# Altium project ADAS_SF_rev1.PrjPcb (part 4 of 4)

## Sheet ADAS_SF_Data_Connection_Radar_02.SchDoc
size 431 x 279 mm; Date: Not shown in title block; ApprovedBy: Not shown in title block; CheckedBy: Not shown in title block; Author: Not shown in title block; CompanyName: Not shown in title block; Engineer: Not shown in title block; Organization: Not shown in title block; Address1: Not shown in title block; Address2: Not shown in title block; Address3: Not shown in title block; Address4: Not shown in title block; DocumentNumber: 1; Revision: Use project parameter SCH_Rev; SheetNumber: 11; SheetTotal: 15; PageSetup: Record=PageOptions¦CenterHorizontal=True¦CenterVertical=True¦PrintScale=1.00¦XCorrection=1.00¦YCorrection=1.00¦PrintKind=0¦BorderSize=5000000¦LeftOffset=0¦BottomOffset=0¦Orientation=2¦PaperLength=1000¦PaperWidth=1000¦Scale=100¦PaperSource=15¦PrintQuality=600¦MediaType=1¦DitherType=10¦PaperKind=Letter¦PrintScaleMode=1
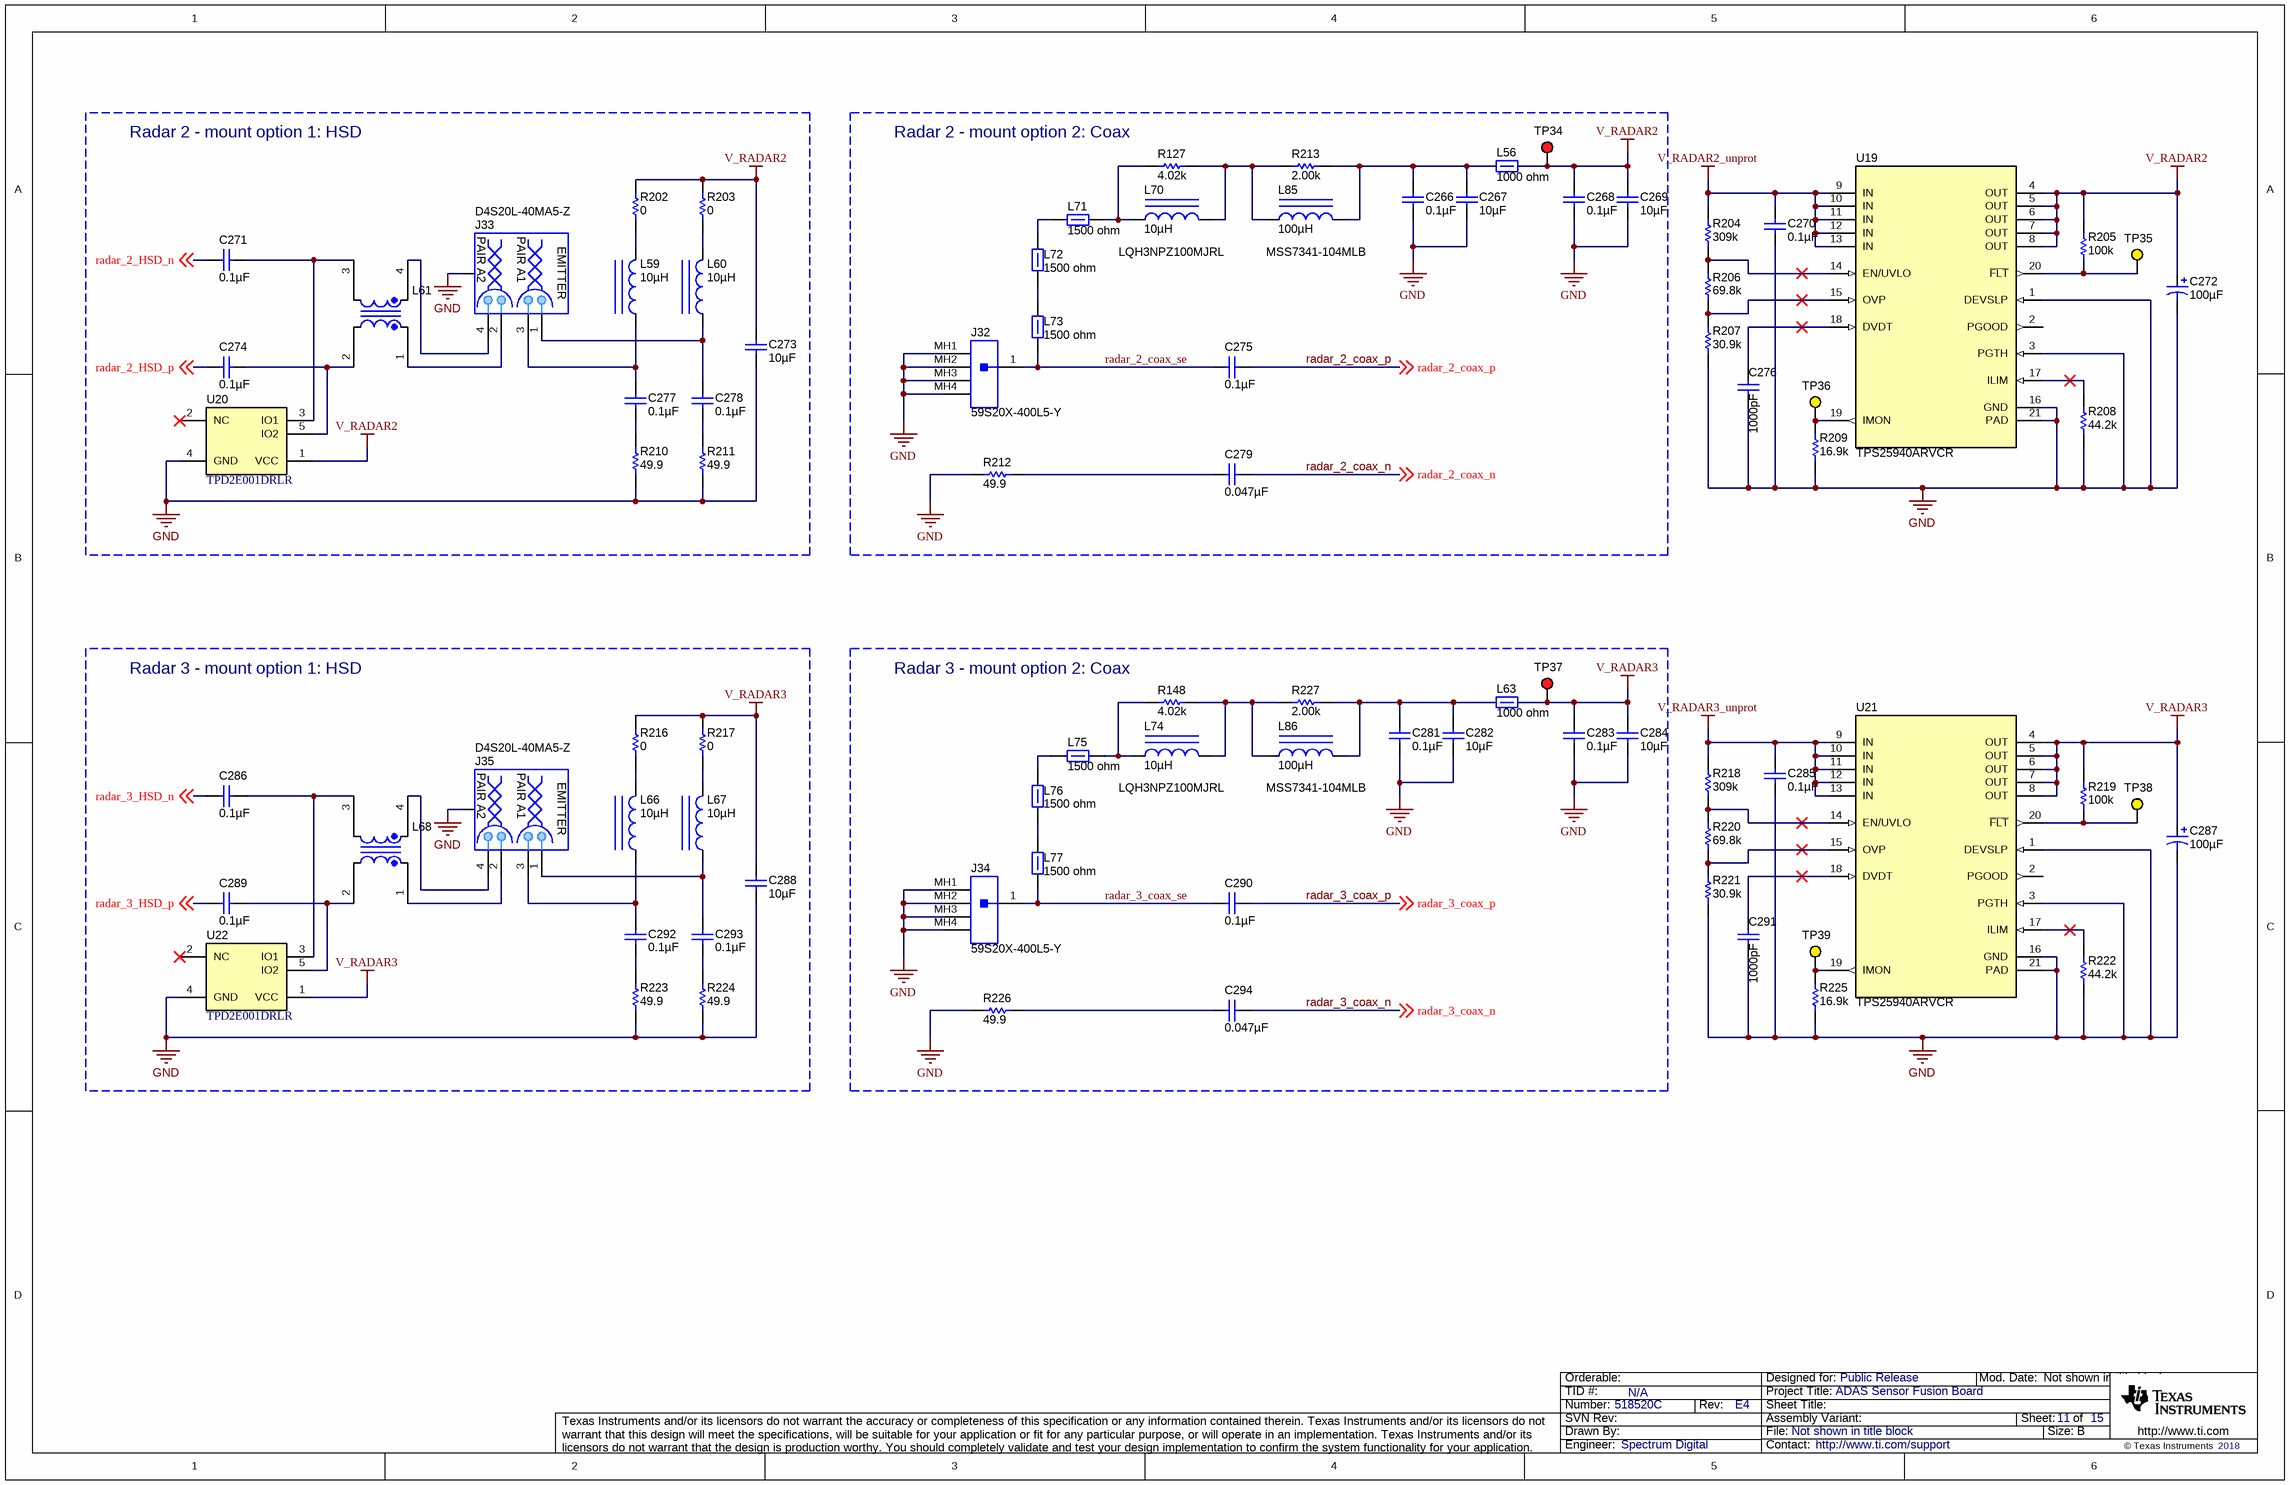
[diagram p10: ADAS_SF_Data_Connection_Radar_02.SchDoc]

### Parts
C266  ValueDisplayed: 0.1µF  [0402]  (hidden comment: GCM155R71H104KE02D)
C267  ValueDisplayed: 10µF  [0805_HV]  (hidden comment: TMK212BBJ106KG-T)
C268  ValueDisplayed: 0.1µF  [0402]  (hidden comment: GCM155R71H104KE02D)
C269  ValueDisplayed: 10µF  [0805_HV]  (hidden comment: TMK212BBJ106KG-T)
C270  ValueDisplayed: 0.1µF  [0603L]  (hidden comment: GRM188R72A104KA35D)
C271  ValueDisplayed: 0.1µF  [0402]  (hidden comment: GCM155R71H104KE02D)
C272  ValueDisplayed: 100µF  [SM_RADIAL_E]  (hidden comment: EEE-FC1C101P)
C273  ValueDisplayed: 10µF  [0805_HV]  (hidden comment: CL21A106KAFN3NE)
C274  ValueDisplayed: 0.1µF  [0402]  (hidden comment: GCM155R71H104KE02D)
C275  ValueDisplayed: 0.1µF  [0402]  (hidden comment: GCM155R71H104KE02D)
C276  ValueDisplayed: 1000pF  [0402]  (hidden comment: GCM155R71H102KA37D)
C277  ValueDisplayed: 0.1µF  [0603]  (hidden comment: GRM188R72A104KA35D)
C278  ValueDisplayed: 0.1µF  [0603]  (hidden comment: GRM188R72A104KA35D)
C279  ValueDisplayed: 0.047µF  [0402]  (hidden comment: CGA2B3X7R1H473K050BB)
C281  ValueDisplayed: 0.1µF  [0402]  (hidden comment: GCM155R71H104KE02D)
C282  ValueDisplayed: 10µF  [0805_HV]  (hidden comment: TMK212BBJ106KG-T)
C283  ValueDisplayed: 0.1µF  [0402]  (hidden comment: GCM155R71H104KE02D)
C284  ValueDisplayed: 10µF  [0805_HV]  (hidden comment: TMK212BBJ106KG-T)
C285  ValueDisplayed: 0.1µF  [0603L]  (hidden comment: GRM188R72A104KA35D)
C286  ValueDisplayed: 0.1µF  [0402]  (hidden comment: GCM155R71H104KE02D)
C287  ValueDisplayed: 100µF  [SM_RADIAL_E]  (hidden comment: EEE-FC1C101P)
C288  ValueDisplayed: 10µF  [0805_HV]  (hidden comment: CL21A106KAFN3NE)
C289  ValueDisplayed: 0.1µF  [0402]  (hidden comment: GCM155R71H104KE02D)
C290  ValueDisplayed: 0.1µF  [0402]  (hidden comment: GCM155R71H104KE02D)
C291  ValueDisplayed: 1000pF  [0402]  (hidden comment: GCM155R71H102KA37D)
C292  ValueDisplayed: 0.1µF  [0603]  (hidden comment: GRM188R72A104KA35D)
C293  ValueDisplayed: 0.1µF  [0603]  (hidden comment: GRM188R72A104KA35D)
C294  ValueDisplayed: 0.047µF  [0402]  (hidden comment: CGA2B3X7R1H473K050BB)
J32  59S20X-400L5-Y  [Rosenberger_59S20X-400L5]
J33  D4S20L-40MA5-Z  [Rosenberger_D4S20L-40MA5]
J34  59S20X-400L5-Y  [Rosenberger_59S20X-400L5]
J35  D4S20L-40MA5-Z  [Rosenberger_D4S20L-40MA5]
L56  value 1000 ohm  [0603]  (hidden comment: MPZ1608S102ATA00)
L59  ValueDisplayed: 10µH  [EPL3012]  (hidden comment: EPL3012-103MLB)
L60  ValueDisplayed: 10µH  [EPL3012]  (hidden comment: EPL3012-103MLB)
L61  DLW21HN900SQ2L  [DLW21H]  (value not drawn)
L63  value 1000 ohm  [0603]  (hidden comment: MPZ1608S102ATA00)
L66  ValueDisplayed: 10µH  [EPL3012]  (hidden comment: EPL3012-103MLB)
L67  ValueDisplayed: 10µH  [EPL3012]  (hidden comment: EPL3012-103MLB)
L68  DLW21HN900SQ2L  [DLW21H]  (value not drawn)
L70  LQH3NPZ100MJRL  ValueDisplayed: 10µH  [LQH3NPZ_JR]
L71  ValueDisplayed: 1500 ohm  [0603]  (hidden comment: BLM18HE152SN1D)
L72  ValueDisplayed: 1500 ohm  [0603]  (hidden comment: BLM18HE152SN1D)
L73  ValueDisplayed: 1500 ohm  [0603]  (hidden comment: BLM18HE152SN1D)
L74  LQH3NPZ100MJRL  ValueDisplayed: 10µH  [LQH3NPZ_JR]
L75  ValueDisplayed: 1500 ohm  [0603]  (hidden comment: BLM18HE152SN1D)
L76  ValueDisplayed: 1500 ohm  [0603]  (hidden comment: BLM18HE152SN1D)
L77  ValueDisplayed: 1500 ohm  [0603]  (hidden comment: BLM18HE152SN1D)
L85  MSS7341-104MLB  ValueDisplayed: 100µH  [MSS7341]
L86  MSS7341-104MLB  ValueDisplayed: 100µH  [MSS7341]
R127  ValueDisplayed: 4.02k  [0603]  (hidden comment: CRCW06034K02FKEA)
R148  ValueDisplayed: 4.02k  [0603]  (hidden comment: CRCW06034K02FKEA)
R202  ValueDisplayed: 0  [0603]  (hidden comment: CRCW06030000Z0EA)
R203  ValueDisplayed: 0  [0603]  (hidden comment: CRCW06030000Z0EA)
R204  ValueDisplayed: 309k  [0402]  (hidden comment: CRCW0402309KFKED)
R205  ValueDisplayed: 100k  [0402]  (hidden comment: CRCW0402100KDHEDP)
R206  ValueDisplayed: 69.8k  [0402]  (hidden comment: CRCW040269K8FKED)
R207  ValueDisplayed: 30.9k  [0402]  (hidden comment: CRCW040230K9FKED)
R208  ValueDisplayed: 44.2k  [0402]  (hidden comment: CRCW040244K2FKED)
R209  ValueDisplayed: 16.9k  [0402]  (hidden comment: CRCW040216K9FKED)
R210  ValueDisplayed: 49.9  [0402]  (hidden comment: CRCW040249R9FKED)
R211  ValueDisplayed: 49.9  [0402]  (hidden comment: CRCW040249R9FKED)
R212  ValueDisplayed: 49.9  [0402]  (hidden comment: CRCW040249R9FKED)
R213  ValueDisplayed: 2.00k  [0603]  (hidden comment: CRCW06032K00FKEA)
R216  ValueDisplayed: 0  [0603]  (hidden comment: CRCW06030000Z0EA)
R217  ValueDisplayed: 0  [0603]  (hidden comment: CRCW06030000Z0EA)
R218  ValueDisplayed: 309k  [0402]  (hidden comment: CRCW0402309KFKED)
R219  ValueDisplayed: 100k  [0402]  (hidden comment: CRCW0402100KDHEDP)
R220  ValueDisplayed: 69.8k  [0402]  (hidden comment: CRCW040269K8FKED)
R221  ValueDisplayed: 30.9k  [0402]  (hidden comment: CRCW040230K9FKED)
R222  ValueDisplayed: 44.2k  [0402]  (hidden comment: CRCW040244K2FKED)
R223  ValueDisplayed: 49.9  [0402]  (hidden comment: CRCW040249R9FKED)
R224  ValueDisplayed: 49.9  [0402]  (hidden comment: CRCW040249R9FKED)
R225  ValueDisplayed: 16.9k  [0402]  (hidden comment: CRCW040216K9FKED)
R226  ValueDisplayed: 49.9  [0402]  (hidden comment: CRCW040249R9FKED)
R227  ValueDisplayed: 2.00k  [0603]  (hidden comment: CRCW06032K00FKEA)
TP34  5000  [Keystone5000]  (value not drawn)
TP35  5004  [Keystone5004]  (value not drawn)
TP36  5004  [Keystone5004]  (value not drawn)
TP37  5000  [Keystone5000]  (value not drawn)
TP38  5004  [Keystone5004]  (value not drawn)
TP39  5004  [Keystone5004]  (value not drawn)
U19  TPS25940ARVCR  [RVC0020A]
U20  TPD2E001DRLR  [DRL0005A]
U21  TPS25940ARVCR  [RVC0020A]
U22  TPD2E001DRLR  [DRL0005A]

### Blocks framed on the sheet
Radar 2 - mount option 1: HSD: C271 C273 C274 C277 C278 J33 L59-L61 R202 R203 R210 R211 U20
Radar 2 - mount option 2: Coax: C266-C269 C275 C279 J32 L56 L70-L73 L85 R127 R212 R213 TP34
Radar 3 - mount option 1: HSD: C286 C288 C289 C292 C293 J35 L66-L68 R216 R217 R223 R224 U22
Radar 3 - mount option 2: Coax: C281-C284 C290 C294 J34 L63 L74-L77 L86 R148 R226 R227 TP37

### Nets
GND: C266.2 C267.2 C268.2 C269.2 C270.1 C272.2(-) C273.2 C276.2 C281.2 C282.2 C283.2 C284.2 C285.1 C287.2(-) C288.2 C291.2 J32.MH1 J32.MH2 J32.MH3 J32.MH4 J33.MH J34.MH1 J34.MH2 J34.MH3 J34.MH4 J35.MH R207.1 R208.1 R209.1 R210.1 R211.1 R212.1 R221.1 R222.1 R223.1 R224.1 R225.1 R226.1 U19.1(DEVSLP) U19.3(PGTH) U19.16(GND) U19.21(PAD) U20.4(GND) U21.1(DEVSLP) U21.3(PGTH) U21.16(GND) U21.21(PAD) U22.4(GND)
V_RADAR2: C268.1 C269.1 C272.1(+) C273.1 L56.2 R202.2 R203.2 R205.2 TP34.1 U19.4(OUT) U19.5(OUT) U19.6(OUT) U19.7(OUT) U19.8(OUT) U20.1(VCC)
V_RADAR2_unprot: C270.2 R204.2 U19.9(IN) U19.10(IN) U19.11(IN) U19.12(IN) U19.13(IN)
V_RADAR3: C283.1 C284.1 C287.1(+) C288.1 L63.2 R216.2 R217.2 R219.2 TP37.1 U21.4(OUT) U21.5(OUT) U21.6(OUT) U21.7(OUT) U21.8(OUT) U22.1(VCC)
V_RADAR3_unprot: C285.2 R218.2 U21.9(IN) U21.10(IN) U21.11(IN) U21.12(IN) U21.13(IN)
radar_2_coax_n: C279.2 ; off-sheet radar_2_coax_n
radar_2_coax_p: C275.1 ; off-sheet radar_2_coax_p
radar_2_coax_se: C275.2 J32.1 L73.1
radar_2_HSD_n: C271.2 ; off-sheet radar_2_HSD_n
radar_2_HSD_p: C274.2 ; off-sheet radar_2_HSD_p
radar_3_coax_n: C294.2 ; off-sheet radar_3_coax_n
radar_3_coax_p: C290.1 ; off-sheet radar_3_coax_p
radar_3_coax_se: C290.2 J34.1 L77.1
radar_3_HSD_n: C286.2 ; off-sheet radar_3_HSD_n
radar_3_HSD_p: C289.2 ; off-sheet radar_3_HSD_p
NetC266_1: C266.1 C267.1 L56.1 L85.2 R213.2
NetC271_1: C271.1 L61.3 U20.3(IO1)
NetC274_1: C274.1 L61.2 U20.5(IO2)
NetC276_1: C276.1 U19.18(DVDT)
NetC277_1: C277.1 J33.3 L59.1
NetC277_2: C277.2 R210.2
NetC278_1: C278.1 J33.1 L60.1
NetC278_2: C278.2 R211.2
NetC279_1: C279.1 R212.2
NetC281_1: C281.1 C282.1 L63.1 L86.2 R227.2
NetC286_1: C286.1 L68.3 U22.3(IO1)
NetC289_1: C289.1 L68.2 U22.5(IO2)
NetC291_1: C291.1 U21.18(DVDT)
NetC292_1: C292.1 J35.3 L66.1
NetC292_2: C292.2 R223.2
NetC293_1: C293.1 J35.1 L67.1
NetC293_2: C293.2 R224.2
NetC294_1: C294.1 R226.2
NetJ33_2: J33.2 L61.1
NetJ33_4: J33.4 L61.4
NetJ35_2: J35.2 L68.1
NetJ35_4: J35.4 L68.4
NetL59_2: L59.2 R202.1
NetL60_2: L60.2 R203.1
NetL66_2: L66.2 R216.1
NetL67_2: L67.2 R217.1
NetL70_1: L70.1 L71.2 R127.1
NetL70_2: L70.2 L85.1 R127.2 R213.1
NetL71_1: L71.1 L72.2
NetL72_1: L72.1 L73.2
NetL74_1: L74.1 L75.2 R148.1
NetL74_2: L74.2 L86.1 R148.2 R227.1
NetL75_1: L75.1 L76.2
NetL76_1: L76.1 L77.2
NetR204_1: R204.1 R206.2 U19.14(EN/UVLO)
NetR205_1: R205.1 TP35.1 U19.20(~{FLT})
NetR206_1: R206.1 R207.2 U19.15(OVP)
NetR208_2: R208.2 U19.17(ILIM)
NetR209_2: R209.2 TP36.1 U19.19(IMON)
NetR218_1: R218.1 R220.2 U21.14(EN/UVLO)
NetR219_1: R219.1 TP38.1 U21.20(~{FLT})
NetR220_1: R220.1 R221.2 U21.15(OVP)
NetR222_2: R222.2 U21.17(ILIM)
NetR225_2: R225.2 TP39.1 U21.19(IMON)

Not connected (* = marked no-connect by the designer): U19 2(PGOOD); U20 2(NC)*; U21 2(PGOOD); U22 2(NC)*

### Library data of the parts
C266 C268 C271 C274 C275 C281 C283 C286 C289 C290 = GCM155R71H104KE02D: CAP, CERM, 0.1 µF, 50 V, +/- 10%, X7R, AEC-Q200 Grade 1, 0402; Manufacturer: MuRata; Polarized: N; CompType: Capacitor; Value: 0.1uF; U/M: EA; Cap_F: 0.0000001; Tolerance_%: 10; Value1: Unknown; VDC_V: 50; Value2: 50V; TaMin_C: -55; TaMax_C: 125; SizeArea_mm2: 0.5; SizeAreaWB_mm2: 3; SizeX_mm: 1; SizeZ_mm: 0.6; AEC Category: Q200; AEC Qualified: Y
C267 C269 C282 C284 = TMK212BBJ106KG-T: CAP, CERM, 10 µF, 25 V, +/- 10%, X5R, 0805; Manufacturer: Taiyo Yuden; Polarized: N; CompType: Capacitor; Value: 10uF; U/M: EA; Cap_F: 0.00001; Tolerance_%: 10; Value1: Unknown; VDC_V: 25; Value2: 25V; TaMin_C: -55; TaMax_C: 85; Cap_Case: 0805; SizeArea_mm2: 2.5; SizeAreaWB_mm2: 6.75; SizeX_mm: 2; SizeY_mm: 1.25; SizeZ_mm: 1.45; AEC Category: Q200
C270 C285 = GRM188R72A104KA35D: CAP, CERM, 0.1uF, 100V, +/-10%, X7R, 0603; Manufacturer: MuRata; Polarized: N; CompType: Capacitor; U/M: EA; Cap_F: 0.0000001; Tolerance_%: 10; Value1: Unknown; VDC_V: 100; TaMin_C: -55; TaMax_C: 125; Cap_Case: 0603
C272 C287 = EEE-FC1C101P: CAP, AL, 100 µF, 16 V, +/- 20%, 0.4 ohm, SMD; Manufacturer: Panasonic; Polarized: Y; CompType: Capacitor; Value: 100uF; U/M: EA; Cap_F: 0.0001; Tolerance_%: 20; Value1: 0.4 ohm; VDC_V: 16; Value2: 16V; ESR_ohm: 0.4; IRMS_A: 0.15; TaMin_C: -40; TaMax_C: 105; Cap_Case: E; AEC Category: Q200
C273 C288 = CL21A106KAFN3NE: CAP, CERM, 10 µF, 25 V, +/- 10%, X5R, 0805; Manufacturer: Samsung; Polarized: N; CompType: Capacitor; Value: 10uF; U/M: EA; Cap_F: 0.00001; Tolerance_%: 10; Value1: Unknown; VDC_V: 25; Value2: 25V; TaMin_C: -55; TaMax_C: 85; Cap_Case: 0805
C276 C291 = GCM155R71H102KA37D: CAP, CERM, 1000 pF, 50 V, +/- 10%, X7R, AEC-Q200 Grade 1, 0402; Manufacturer: MuRata; Polarized: N; CompType: Capacitor; Value: 1000pF; U/M: EA; Cap_F: 0.000000001; Tolerance_%: 10; Value1: Unknown; VDC_V: 50; Value2: 50V; TaMin_C: -55; TaMax_C: 125; SizeArea_mm2: 0.5; SizeAreaWB_mm2: 3; SizeX_mm: 1; SizeZ_mm: 0.6; AEC Category: Q200; AEC Qualified: Y
C277 C278 C292 C293 = GRM188R72A104KA35D: CAP, CERM, 0.1 µF, 100 V, +/- 10%, X7R, 0603; Manufacturer: MuRata; Polarized: N; CompType: Capacitor; Value: 0.1uF; U/M: EA; Cap_F: 0.0000001; Tolerance_%: 10; Value1: Unknown; VDC_V: 100; Value2: 100V; TaMin_C: -55; TaMax_C: 125; SizeArea_mm2: 1.28; SizeAreaWB_mm2: 4.68; SizeX_mm: 1.6; SizeY_mm: 0.8; SizeZ_mm: 1; AEC Category: Q200
C279 C294 = CGA2B3X7R1H473K050BB: CAP, CERM, 0.047 µF, 50 V, +/- 10%, X7R, AEC-Q200 Grade 1, 0402; Manufacturer: TDK; Polarized: N; CompType: Capacitor; Value: 0.047uF; U/M: EA; Cap_F: 0.000000047; Tolerance_%: 10; ESR_ohm: 0.06407; Value1: 0.06407 ohm; VDC_V: 50; Value2: 50V; IRMS_A: 0.646122; TaMin_C: -55; TaMax_C: 125; SizeArea_mm2: 0.5; SizeAreaWB_mm2: 3; SizeX_mm: 1; SizeZ_mm: 0.6; AEC Category: Q200; AEC Qualified: Y
J32 J34 = 59S20X-400L5-Y: RIGHT ANGLE PLUG FOR PCB; Manufacturer: Rosenberger; SymbolCreator: x0208325; U/M: EA
J33 J35 = D4S20L-40MA5-Z: Right Angle Plug for PCB, TH; Manufacturer: Rosenberger; SymbolCreator: Altium/a0412235
L56 L63 = MPZ1608S102ATA00: Ferrite Bead, 1000 ohm @ 100 MHz, 0.8 A, 0603; Manufacturer: TDK; Imax_A: 0.8; DCR_ohm: 0.3; Value1: 0.3 ohm; Value2: 0.8A; ZTyp@100MHz_Ohm: 1000
L59 L60 L66 L67 = EPL3012-103MLB: Inductor, Shielded, Ferrite, 10 µH, 0.79 A, 0.32 ohm, SMD; Manufacturer: Coilcraft; Value: 10uH; Ind_H: 10.0E-6; Imax_A: 0.79; Irms: 0.79A @ 40C rise; Isat: 0.8A @ 30% inductance drop; DCR_ohm: 0.32; Value2: 0.79A; AEC Category: Q200
L61 L68 = DLW21HN900SQ2L: Coupled inductor, 0.33 A, 0.35 ohm, SMD; Manufacturer: MuRata; SymbolCreator: a0412235; DCR_ohm: 0.35
L70 L74 = LQH3NPZ100MJRL: Inductor, Wirewound, Ferrite, 10 µH, 0.81 A, 0.288 ohm, AEC-Q200 Grade 1, SMD; Manufacturer: MuRata; Value: 10uH; Ind_H: 10.0E-6; Imax_A: 0.81; Irms: 1.2A @ 40C rise; Isat: 0.81A @ 30% inductance drop; DCR_ohm: 0.288; Value2: 0.81A; SizeAreaWB_mm2: 16; SizeArea_mm2: 9; SizeX_mm: 3; SizeZ_mm: 1.2; AEC Category: Q200; AEC Qualified: Y; AEC Grade: 1
L71-L73 L75-L77 = BLM18HE152SN1D: Ferrite Bead, 1500 ohm @ 100 MHz, 0.5 A, 0603; Manufacturer: MuRata; Imax_A: 0.5; Value1: 0.5 ohm; Value2: 0.5A; SizeAreaWB_mm2: 4.68; SizeArea_mm2: 1.28; SizeX_mm: 1.6; SizeY_mm: 0.8; SizeZ_mm: 1; ZTyp@100MHz_Ohm: 1500
L85 L86 = MSS7341-104MLB: Inductor, Shielded Drum Core, Ferrite, 100 µH, 0.71 A, 0.36 ohm, SMD; Manufacturer: Coilcraft; Value: 100uH; Ind_H: 100.0E-6; Imax_A: 0.71; Irms: 1.15A @ 40C rise; Isat: 0.71A @ 30% inductance drop; DCR_ohm: 0.36; Value2: 0.71A; SizeAreaWB_mm2: 86.49; SizeArea_mm2: 53.29; SizeX_mm: 7.3; SizeZ_mm: 4.1; AEC Category: Q200; AEC Qualified: N
R127 R148 = CRCW06034K02FKEA: RES, 4.02 k, 1%, 0.1 W, 0603; Manufacturer: Vishay-Dale; CompType: Resistor; Value: 4.02k; Res_ohm: 4020; Value_Code: 4k02; Tolerance_%: 1; Power_W: 0.1; Value2: 0.1W; VDC_V: 75; TempCo: 100 ppm/C; SizeArea_mm2: 1.28; SizeX_mm: 1.6; SizeY_mm: 0.8; EIA_Code: E96; U/M: EA; AEC Category: Q200
R202 R203 R216 R217 = CRCW06030000Z0EA: RES, 0, 5%, 0.1 W, 0603; Manufacturer: Vishay-Dale; CompType: Resistor; Value: 0; Value_Code: 0000; Tolerance_%: 5; Power_W: 0.1; Value2: 0.1W; VDC_V: 75; TempCo: 200 ppm/C; SizeArea_mm2: 1.28; SizeX_mm: 1.6; SizeY_mm: 0.8; SizeZ_mm: 1; EIA_Code: E24; U/M: EA; AEC Category: Q200
R204 R218 = CRCW0402309KFKED: RES, 309 k, 1%, 0.063 W, 0402; Manufacturer: Vishay-Dale; CompType: Resistor; Value: 309k; Res_ohm: 309000; Tolerance_%: 1; Power_W: 0.063; Value2: 0.063W; VDC_V: 50; TempCo: 100 ppm/C; SizeArea_mm2: 0.5; SizeZ_mm: 0.6; EIA_Code: E96; U/M: EA; AEC Category: Q200
R205 R219 = CRCW0402100KDHEDP: RES, 100 k, 0.5%, 0.063 W, 0402; Manufacturer: Vishay-Dale; CompType: Resistor; Value: 100k; Res_ohm: 100000; Tolerance_%: 0.5; Power_W: 0.063; Value2: 0.063W; VDC_V: 50; TempCo: 50 ppm/C; SizeX_mm: 1; SizeZ_mm: 0.6; EIA_Code: E192; U/M: EA; AEC Category: Q200
R206 R220 = CRCW040269K8FKED: RES, 69.8 k, 1%, 0.063 W, 0402; Manufacturer: Vishay-Dale; CompType: Resistor; Value: 69.8k; Res_ohm: 69800; Value_Code: 69k8; Tolerance_%: 1; Power_W: 0.063; Value2: 0.063W; VDC_V: 50; TempCo: 100 ppm/C; SizeArea_mm2: 0.5; SizeZ_mm: 0.6; EIA_Code: E96; U/M: EA; AEC Category: Q200
R207 R221 = CRCW040230K9FKED: RES, 30.9 k, 1%, 0.063 W, 0402; Manufacturer: Vishay-Dale; CompType: Resistor; Value: 30.9k; Res_ohm: 30900; Value_Code: 30k9; Tolerance_%: 1; Power_W: 0.063; Value2: 0.063W; VDC_V: 50; TempCo: 100 ppm/C; SizeArea_mm2: 0.5; SizeZ_mm: 0.6; EIA_Code: E96; U/M: EA; AEC Category: Q200
R208 R222 = CRCW040244K2FKED: RES, 44.2 k, 1%, 0.063 W, 0402; Manufacturer: Vishay-Dale; CompType: Resistor; Value: 44.2k; Res_ohm: 44200; Value_Code: 44k2; Tolerance_%: 1; Power_W: 0.063; Value2: 0.063W; VDC_V: 50; TempCo: 100 ppm/C; SizeArea_mm2: 0.5; SizeZ_mm: 0.6; EIA_Code: E96; U/M: EA; AEC Category: Q200
R209 R225 = CRCW040216K9FKED: RES, 16.9 k, 1%, 0.063 W, 0402; Manufacturer: Vishay-Dale; CompType: Resistor; Value: 16.9k; Res_ohm: 16900; Value_Code: 16k9; Tolerance_%: 1; Power_W: 0.063; Value2: 0.063W; VDC_V: 50; TempCo: 100 ppm/C; SizeArea_mm2: 0.5; SizeZ_mm: 0.6; EIA_Code: E96; U/M: EA; AEC Category: Q200
R210 R211 R223 R224 = CRCW040249R9FKED: RES, 49.9, 1%, 0.063 W, 0402; Manufacturer: Vishay-Dale; CompType: Resistor; Value: 49.9; Value_Code: 49R9; Tolerance_%: 1; Power_W: 0.063; Value2: 0.063W; VDC_V: 50; TempCo: 100 ppm/C; SizeArea_mm2: 0.5; SizeZ_mm: 0.6; EIA_Code: E96; U/M: EA; AEC Category: Q200
R212 R226 = CRCW040249R9FKED: RES, 49.9, 1%, 0.063 W, 0402; Manufacturer: Vishay-Dale; CompType: Resistor; Value: 49.9; Value_Code: 49R9; Tolerance_%: 1; Power_W: 0.063; Value2: 0.063W; VDC_V: 50; TempCo: 100 ppm/C; EIA_Code: E96; U/M: EA; SizeArea_mm2: 0.5; SizeZ_mm: 0.6; AEC Category: Q200
R213 R227 = CRCW06032K00FKEA: RES, 2.00 k, 1%, 0.1 W, 0603; Manufacturer: Vishay-Dale; CompType: Resistor; Value: 2.00k; Res_ohm: 2000; Value_Code: 2k00; Tolerance_%: 1; Power_W: 0.1; Value2: 0.1W; VDC_V: 75; TempCo: 100 ppm/C; SizeArea_mm2: 1.28; SizeX_mm: 1.6; SizeY_mm: 0.8; EIA_Code: E96; U/M: EA; AEC Category: Q200
TP34 TP37 = 5000: Test Point, Miniature, Red, TH; Manufacturer: Keystone; CompType: Test Point Loop; U/M: EA
TP35 TP36 TP38 TP39 = 5004: Test Point, Miniature, Yellow, TH; Manufacturer: Keystone; CompType: Test Point Loop; U/M: EA
U19 U21 = TPS25940ARVCR: 2.7 – 18V eFuse with True Reverse Blocking and DevSleep Support for SSDs, RVC0020A; Alternate PartNumber: TPS25940ARVCT; Manufacturer: Texas Instruments; SymbolCreator: a0411947; SizeArea_mm2: 12; SizeAreaWB_mm2: 20; SizeX_mm: 3; SizeY_mm: 4; SizeZ_mm: 0.8; CompType: IC; U/M: EA
U20 U22 = TPD2E001DRLR: Low-Capacitance + / - 15 kV ESD-Protection Array for High-Speed Data Interfaces, 2 Channels, -40 to +85 degC, 5-pin SOT (DRL), Green (RoHS & no Sb/Br); Manufacturer: Texas Instruments; Alternate PartNumber: Equivalent; Breakdown Voltage(Min)(V): 11; IEC 61000-4-2 Air-Gap(+/- kV): 15; IEC 61000-4-2 Contact(+/- kV): 8; IO Capacitance(Typ)(pF): 1.5; IO Leakage Current(nA): 1; SubFamily: ESD Solution; USB High Speed: TRUE

## Sheet ADAS_SF_Data_Connection_Cam_01.SchDoc
size 431 x 279 mm; Date: Not shown in title block; ApprovedBy: Not shown in title block; CheckedBy: Not shown in title block; Author: Not shown in title block; CompanyName: Not shown in title block; Engineer: Not shown in title block; Organization: Not shown in title block; Address1: Not shown in title block; Address2: Not shown in title block; Address3: Not shown in title block; Address4: Not shown in title block; DocumentNumber: 1; Revision: Use project parameter SCH_Rev; SheetNumber: 12; SheetTotal: 15; PageSetup: Record=PageOptions¦CenterHorizontal=True¦CenterVertical=True¦PrintScale=1.00¦XCorrection=1.00¦YCorrection=1.00¦PrintKind=0¦BorderSize=5000000¦LeftOffset=0¦BottomOffset=0¦Orientation=2¦PaperLength=1000¦PaperWidth=1000¦Scale=100¦PaperSource=15¦PrintQuality=600¦MediaType=1¦DitherType=10¦PaperKind=Letter¦PrintScaleMode=1
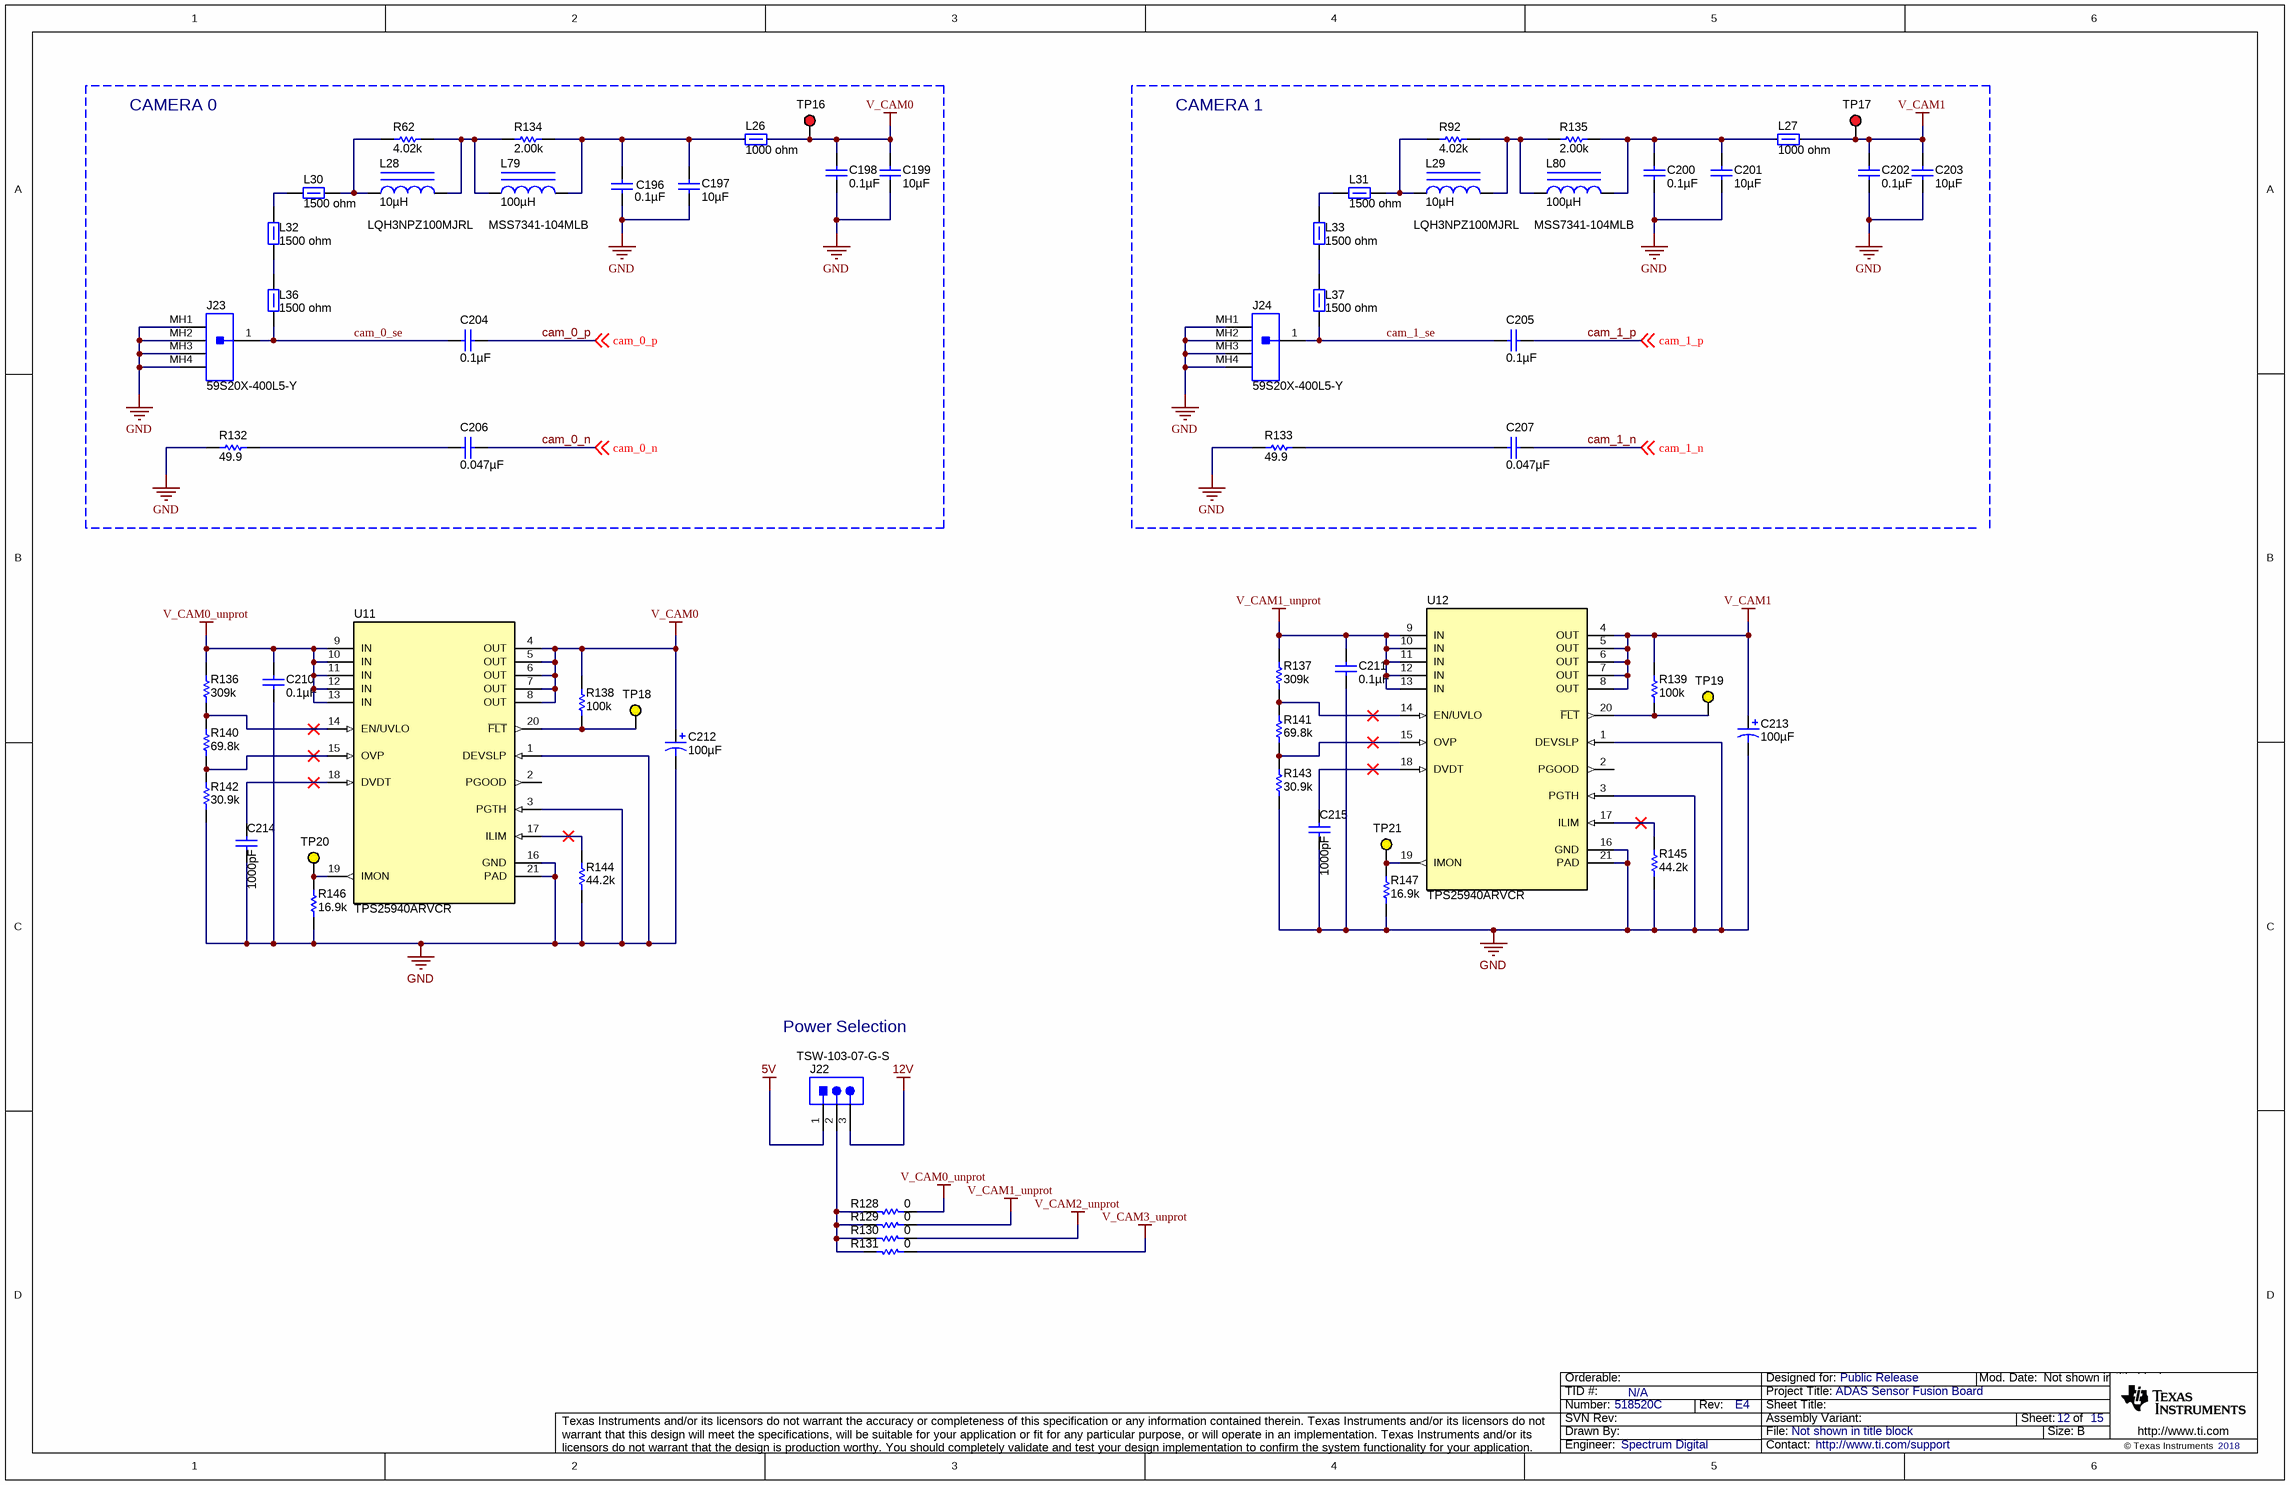
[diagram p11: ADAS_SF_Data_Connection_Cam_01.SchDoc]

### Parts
C196  ValueDisplayed: 0.1µF  [0402]  (hidden comment: GCM155R71H104KE02D)
C197  ValueDisplayed: 10µF  [0805_HV]  (hidden comment: TMK212BBJ106KG-T)
C198  ValueDisplayed: 0.1µF  [0402]  (hidden comment: GCM155R71H104KE02D)
C199  ValueDisplayed: 10µF  [0805_HV]  (hidden comment: TMK212BBJ106KG-T)
C200  ValueDisplayed: 0.1µF  [0402]  (hidden comment: GCM155R71H104KE02D)
C201  ValueDisplayed: 10µF  [0805_HV]  (hidden comment: TMK212BBJ106KG-T)
C202  ValueDisplayed: 0.1µF  [0402]  (hidden comment: GCM155R71H104KE02D)
C203  ValueDisplayed: 10µF  [0805_HV]  (hidden comment: TMK212BBJ106KG-T)
C204  ValueDisplayed: 0.1µF  [0402]  (hidden comment: GCM155R71H104KE02D)
C205  ValueDisplayed: 0.1µF  [0402]  (hidden comment: GCM155R71H104KE02D)
C206  ValueDisplayed: 0.047µF  [0402]  (hidden comment: CGA2B3X7R1H473K050BB)
C207  ValueDisplayed: 0.047µF  [0402]  (hidden comment: CGA2B3X7R1H473K050BB)
C210  ValueDisplayed: 0.1µF  [0603L]  (hidden comment: GRM188R72A104KA35D)
C211  ValueDisplayed: 0.1µF  [0603L]  (hidden comment: GRM188R72A104KA35D)
C212  ValueDisplayed: 100µF  [SM_RADIAL_E]  (hidden comment: EEE-FC1C101P)
C213  ValueDisplayed: 100µF  [SM_RADIAL_E]  (hidden comment: EEE-FC1C101P)
C214  ValueDisplayed: 1000pF  [0402]  (hidden comment: GCM155R71H102KA37D)
C215  ValueDisplayed: 1000pF  [0402]  (hidden comment: GCM155R71H102KA37D)
J22  TSW-103-07-G-S  [TSW-103-07-G-S]
J23  59S20X-400L5-Y  [Rosenberger_59S20X-400L5]
J24  59S20X-400L5-Y  [Rosenberger_59S20X-400L5]
L26  value 1000 ohm  [0603]  (hidden comment: MPZ1608S102ATA00)
L27  value 1000 ohm  [0603]  (hidden comment: MPZ1608S102ATA00)
L28  LQH3NPZ100MJRL  ValueDisplayed: 10µH  [LQH3NPZ_JR]
L29  LQH3NPZ100MJRL  ValueDisplayed: 10µH  [LQH3NPZ_JR]
L30  ValueDisplayed: 1500 ohm  [0603]  (hidden comment: BLM18HE152SN1D)
L31  ValueDisplayed: 1500 ohm  [0603]  (hidden comment: BLM18HE152SN1D)
L32  ValueDisplayed: 1500 ohm  [0603]  (hidden comment: BLM18HE152SN1D)
L33  ValueDisplayed: 1500 ohm  [0603]  (hidden comment: BLM18HE152SN1D)
L36  ValueDisplayed: 1500 ohm  [0603]  (hidden comment: BLM18HE152SN1D)
L37  ValueDisplayed: 1500 ohm  [0603]  (hidden comment: BLM18HE152SN1D)
L79  MSS7341-104MLB  ValueDisplayed: 100µH  [MSS7341]
L80  MSS7341-104MLB  ValueDisplayed: 100µH  [MSS7341]
R62  ValueDisplayed: 4.02k  [0603]  (hidden comment: CRCW06034K02FKEA)
R92  ValueDisplayed: 4.02k  [0603]  (hidden comment: CRCW06034K02FKEA)
R128  value 0  [0603]  (hidden comment: CRCW06030000Z0EA)
R129  value 0  [0603]  (hidden comment: CRCW06030000Z0EA)
R130  value 0  [0603]  (hidden comment: CRCW06030000Z0EA)
R131  value 0  [0603]  (hidden comment: CRCW06030000Z0EA)
R132  ValueDisplayed: 49.9  [0402]  (hidden comment: CRCW040249R9FKED)
R133  ValueDisplayed: 49.9  [0402]  (hidden comment: CRCW040249R9FKED)
R134  ValueDisplayed: 2.00k  [0603]  (hidden comment: CRCW06032K00FKEA)
R135  ValueDisplayed: 2.00k  [0603]  (hidden comment: CRCW06032K00FKEA)
R136  ValueDisplayed: 309k  [0402]  (hidden comment: CRCW0402309KFKED)
R137  ValueDisplayed: 309k  [0402]  (hidden comment: CRCW0402309KFKED)
R138  ValueDisplayed: 100k  [0402]  (hidden comment: CRCW0402100KDHEDP)
R139  ValueDisplayed: 100k  [0402]  (hidden comment: CRCW0402100KDHEDP)
R140  ValueDisplayed: 69.8k  [0402]  (hidden comment: CRCW040269K8FKED)
R141  ValueDisplayed: 69.8k  [0402]  (hidden comment: CRCW040269K8FKED)
R142  ValueDisplayed: 30.9k  [0402]  (hidden comment: CRCW040230K9FKED)
R143  ValueDisplayed: 30.9k  [0402]  (hidden comment: CRCW040230K9FKED)
R144  ValueDisplayed: 44.2k  [0402]  (hidden comment: CRCW040244K2FKED)
R145  ValueDisplayed: 44.2k  [0402]  (hidden comment: CRCW040244K2FKED)
R146  ValueDisplayed: 16.9k  [0402]  (hidden comment: CRCW040216K9FKED)
R147  ValueDisplayed: 16.9k  [0402]  (hidden comment: CRCW040216K9FKED)
TP16  5000  [Keystone5000]  (value not drawn)
TP17  5000  [Keystone5000]  (value not drawn)
TP18  5004  [Keystone5004]  (value not drawn)
TP19  5004  [Keystone5004]  (value not drawn)
TP20  5004  [Keystone5004]  (value not drawn)
TP21  5004  [Keystone5004]  (value not drawn)
U11  TPS25940ARVCR  [RVC0020A]
U12  TPS25940ARVCR  [RVC0020A]

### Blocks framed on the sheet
CAMERA 0: C196-C199 C204 C206 J23 L26 L28 L30 L32 L36 L79 R62 R132 R134 TP16

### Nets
5V: J22.1
12V: J22.3
GND: C196.2 C197.2 C198.2 C199.2 C200.2 C201.2 C202.2 C203.2 C210.1 C211.1 C212.2(-) C213.2(-) C214.2 C215.2 J23.MH1 J23.MH2 J23.MH3 J23.MH4 J24.MH1 J24.MH2 J24.MH3 J24.MH4 R132.1 R133.1 R142.1 R143.1 R144.1 R145.1 R146.1 R147.1 U11.1(DEVSLP) U11.3(PGTH) U11.16(GND) U11.21(PAD) U12.1(DEVSLP) U12.3(PGTH) U12.16(GND) U12.21(PAD)
V_CAM0: C198.1 C199.1 C212.1(+) L26.2 R138.2 TP16.1 U11.4(OUT) U11.5(OUT) U11.6(OUT) U11.7(OUT) U11.8(OUT)
V_CAM0_unprot: C210.2 R128.1 R136.2 U11.9(IN) U11.10(IN) U11.11(IN) U11.12(IN) U11.13(IN)
V_CAM1: C202.1 C203.1 C213.1(+) L27.2 R139.2 TP17.1 U12.4(OUT) U12.5(OUT) U12.6(OUT) U12.7(OUT) U12.8(OUT)
V_CAM1_unprot: C211.2 R129.1 R137.2 U12.9(IN) U12.10(IN) U12.11(IN) U12.12(IN) U12.13(IN)
V_CAM2_unprot: R130.1
V_CAM3_unprot: R131.1
cam_0_n: C206.2 ; off-sheet cam_0_n
cam_0_p: C204.1 ; off-sheet cam_0_p
cam_0_se: C204.2 J23.1 L36.1
cam_1_n: C207.2 ; off-sheet cam_1_n
cam_1_p: C205.1 ; off-sheet cam_1_p
cam_1_se: C205.2 J24.1 L37.1
NetC196_1: C196.1 C197.1 L26.1 L79.2 R134.2
NetC200_1: C200.1 C201.1 L27.1 L80.2 R135.2
NetC206_1: C206.1 R132.2
NetC207_1: C207.1 R133.2
NetC214_1: C214.1 U11.18(DVDT)
NetC215_1: C215.1 U12.18(DVDT)
NetJ22_2: J22.2 R128.2 R129.2 R130.2 R131.2
NetL28_1: L28.1 L30.2 R62.1
NetL28_2: L28.2 L79.1 R62.2 R134.1
NetL29_1: L29.1 L31.2 R92.1
NetL29_2: L29.2 L80.1 R92.2 R135.1
NetL30_1: L30.1 L32.2
NetL31_1: L31.1 L33.2
NetL32_1: L32.1 L36.2
NetL33_1: L33.1 L37.2
NetR136_1: R136.1 R140.2 U11.14(EN/UVLO)
NetR137_1: R137.1 R141.2 U12.14(EN/UVLO)
NetR138_1: R138.1 TP18.1 U11.20(~{FLT})
NetR139_1: R139.1 TP19.1 U12.20(~{FLT})
NetR140_1: R140.1 R142.2 U11.15(OVP)
NetR141_1: R141.1 R143.2 U12.15(OVP)
NetR144_2: R144.2 U11.17(ILIM)
NetR145_2: R145.2 U12.17(ILIM)
NetR146_2: R146.2 TP20.1 U11.19(IMON)
NetR147_2: R147.2 TP21.1 U12.19(IMON)

Not connected (* = marked no-connect by the designer): U11 2(PGOOD); U12 2(PGOOD)

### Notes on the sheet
- CAMERA 1
- Power Selection

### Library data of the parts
C196 C198 C200 C202 C204 C205 = GCM155R71H104KE02D: as C266 on sheet ADAS_SF_Data_Connection_Radar_02
C197 C199 C201 C203 = TMK212BBJ106KG-T: as C267 on sheet ADAS_SF_Data_Connection_Radar_02
C206 C207 = CGA2B3X7R1H473K050BB: as C279 on sheet ADAS_SF_Data_Connection_Radar_02
C210 C211 = GRM188R72A104KA35D: as C270 on sheet ADAS_SF_Data_Connection_Radar_02
C212 C213 = EEE-FC1C101P: as C272 on sheet ADAS_SF_Data_Connection_Radar_02
C214 C215 = GCM155R71H102KA37D: as C276 on sheet ADAS_SF_Data_Connection_Radar_02
J22 = TSW-103-07-G-S: Header, 100mil, 3x1, Gold, TH; Manufacturer: Samtec; SymbolCreator: a0799628; Pitch_mm: 2.54; Gender: Male; Shrouded: N; Row_Count: 1; Current_A: 6.3; Voltage_V: 550; Cert_CSA: Y
J23 J24 = 59S20X-400L5-Y: as J32 on sheet ADAS_SF_Data_Connection_Radar_02
L26 L27 = MPZ1608S102ATA00: as L56 on sheet ADAS_SF_Data_Connection_Radar_02
L28 L29 = LQH3NPZ100MJRL: as L70 on sheet ADAS_SF_Data_Connection_Radar_02
L30-L33 L36 L37 = BLM18HE152SN1D: as L71-L73 on sheet ADAS_SF_Data_Connection_Radar_02
L79 L80 = MSS7341-104MLB: as L85 on sheet ADAS_SF_Data_Connection_Radar_02
R62 R92 = CRCW06034K02FKEA: as R127 on sheet ADAS_SF_Data_Connection_Radar_02
R128-R131 = CRCW06030000Z0EA: RES, 0 ohm, 5%, 0.1W, 0603; Manufacturer: Vishay-Dale; CompType: Resistor; Value_Code: 0000; Tolerance_%: 5; Power_W: 0.1; VDC_V: 75; TempCo: 200 ppm/C; EIA_Code: E24; U/M: EA
R132 R133 = CRCW040249R9FKED: as R212 on sheet ADAS_SF_Data_Connection_Radar_02
R134 R135 = CRCW06032K00FKEA: as R213 on sheet ADAS_SF_Data_Connection_Radar_02
R136 R137 = CRCW0402309KFKED: as R204 on sheet ADAS_SF_Data_Connection_Radar_02
R138 R139 = CRCW0402100KDHEDP: as R205 on sheet ADAS_SF_Data_Connection_Radar_02
R140 R141 = CRCW040269K8FKED: as R206 on sheet ADAS_SF_Data_Connection_Radar_02
R142 R143 = CRCW040230K9FKED: as R207 on sheet ADAS_SF_Data_Connection_Radar_02
R144 R145 = CRCW040244K2FKED: as R208 on sheet ADAS_SF_Data_Connection_Radar_02
R146 R147 = CRCW040216K9FKED: as R209 on sheet ADAS_SF_Data_Connection_Radar_02
TP16 TP17 = 5000: as TP34 on sheet ADAS_SF_Data_Connection_Radar_02
TP18-TP21 = 5004: as TP35 on sheet ADAS_SF_Data_Connection_Radar_02
U11 U12 = TPS25940ARVCR: as U19 on sheet ADAS_SF_Data_Connection_Radar_02

## Sheet ADAS_SF_Data_Connection_Cam_02.SchDoc
size 431 x 279 mm; Date: Not shown in title block; ApprovedBy: Not shown in title block; CheckedBy: Not shown in title block; Author: Not shown in title block; CompanyName: Not shown in title block; Engineer: Not shown in title block; Organization: Not shown in title block; Address1: Not shown in title block; Address2: Not shown in title block; Address3: Not shown in title block; Address4: Not shown in title block; DocumentNumber: 1; Revision: Use project parameter SCH_Rev; SheetNumber: 13; SheetTotal: 15; PageSetup: Record=PageOptions¦CenterHorizontal=True¦CenterVertical=True¦PrintScale=1.00¦XCorrection=1.00¦YCorrection=1.00¦PrintKind=0¦BorderSize=5000000¦LeftOffset=0¦BottomOffset=0¦Orientation=2¦PaperLength=1000¦PaperWidth=1000¦Scale=100¦PaperSource=15¦PrintQuality=600¦MediaType=1¦DitherType=10¦PaperKind=Letter¦PrintScaleMode=1
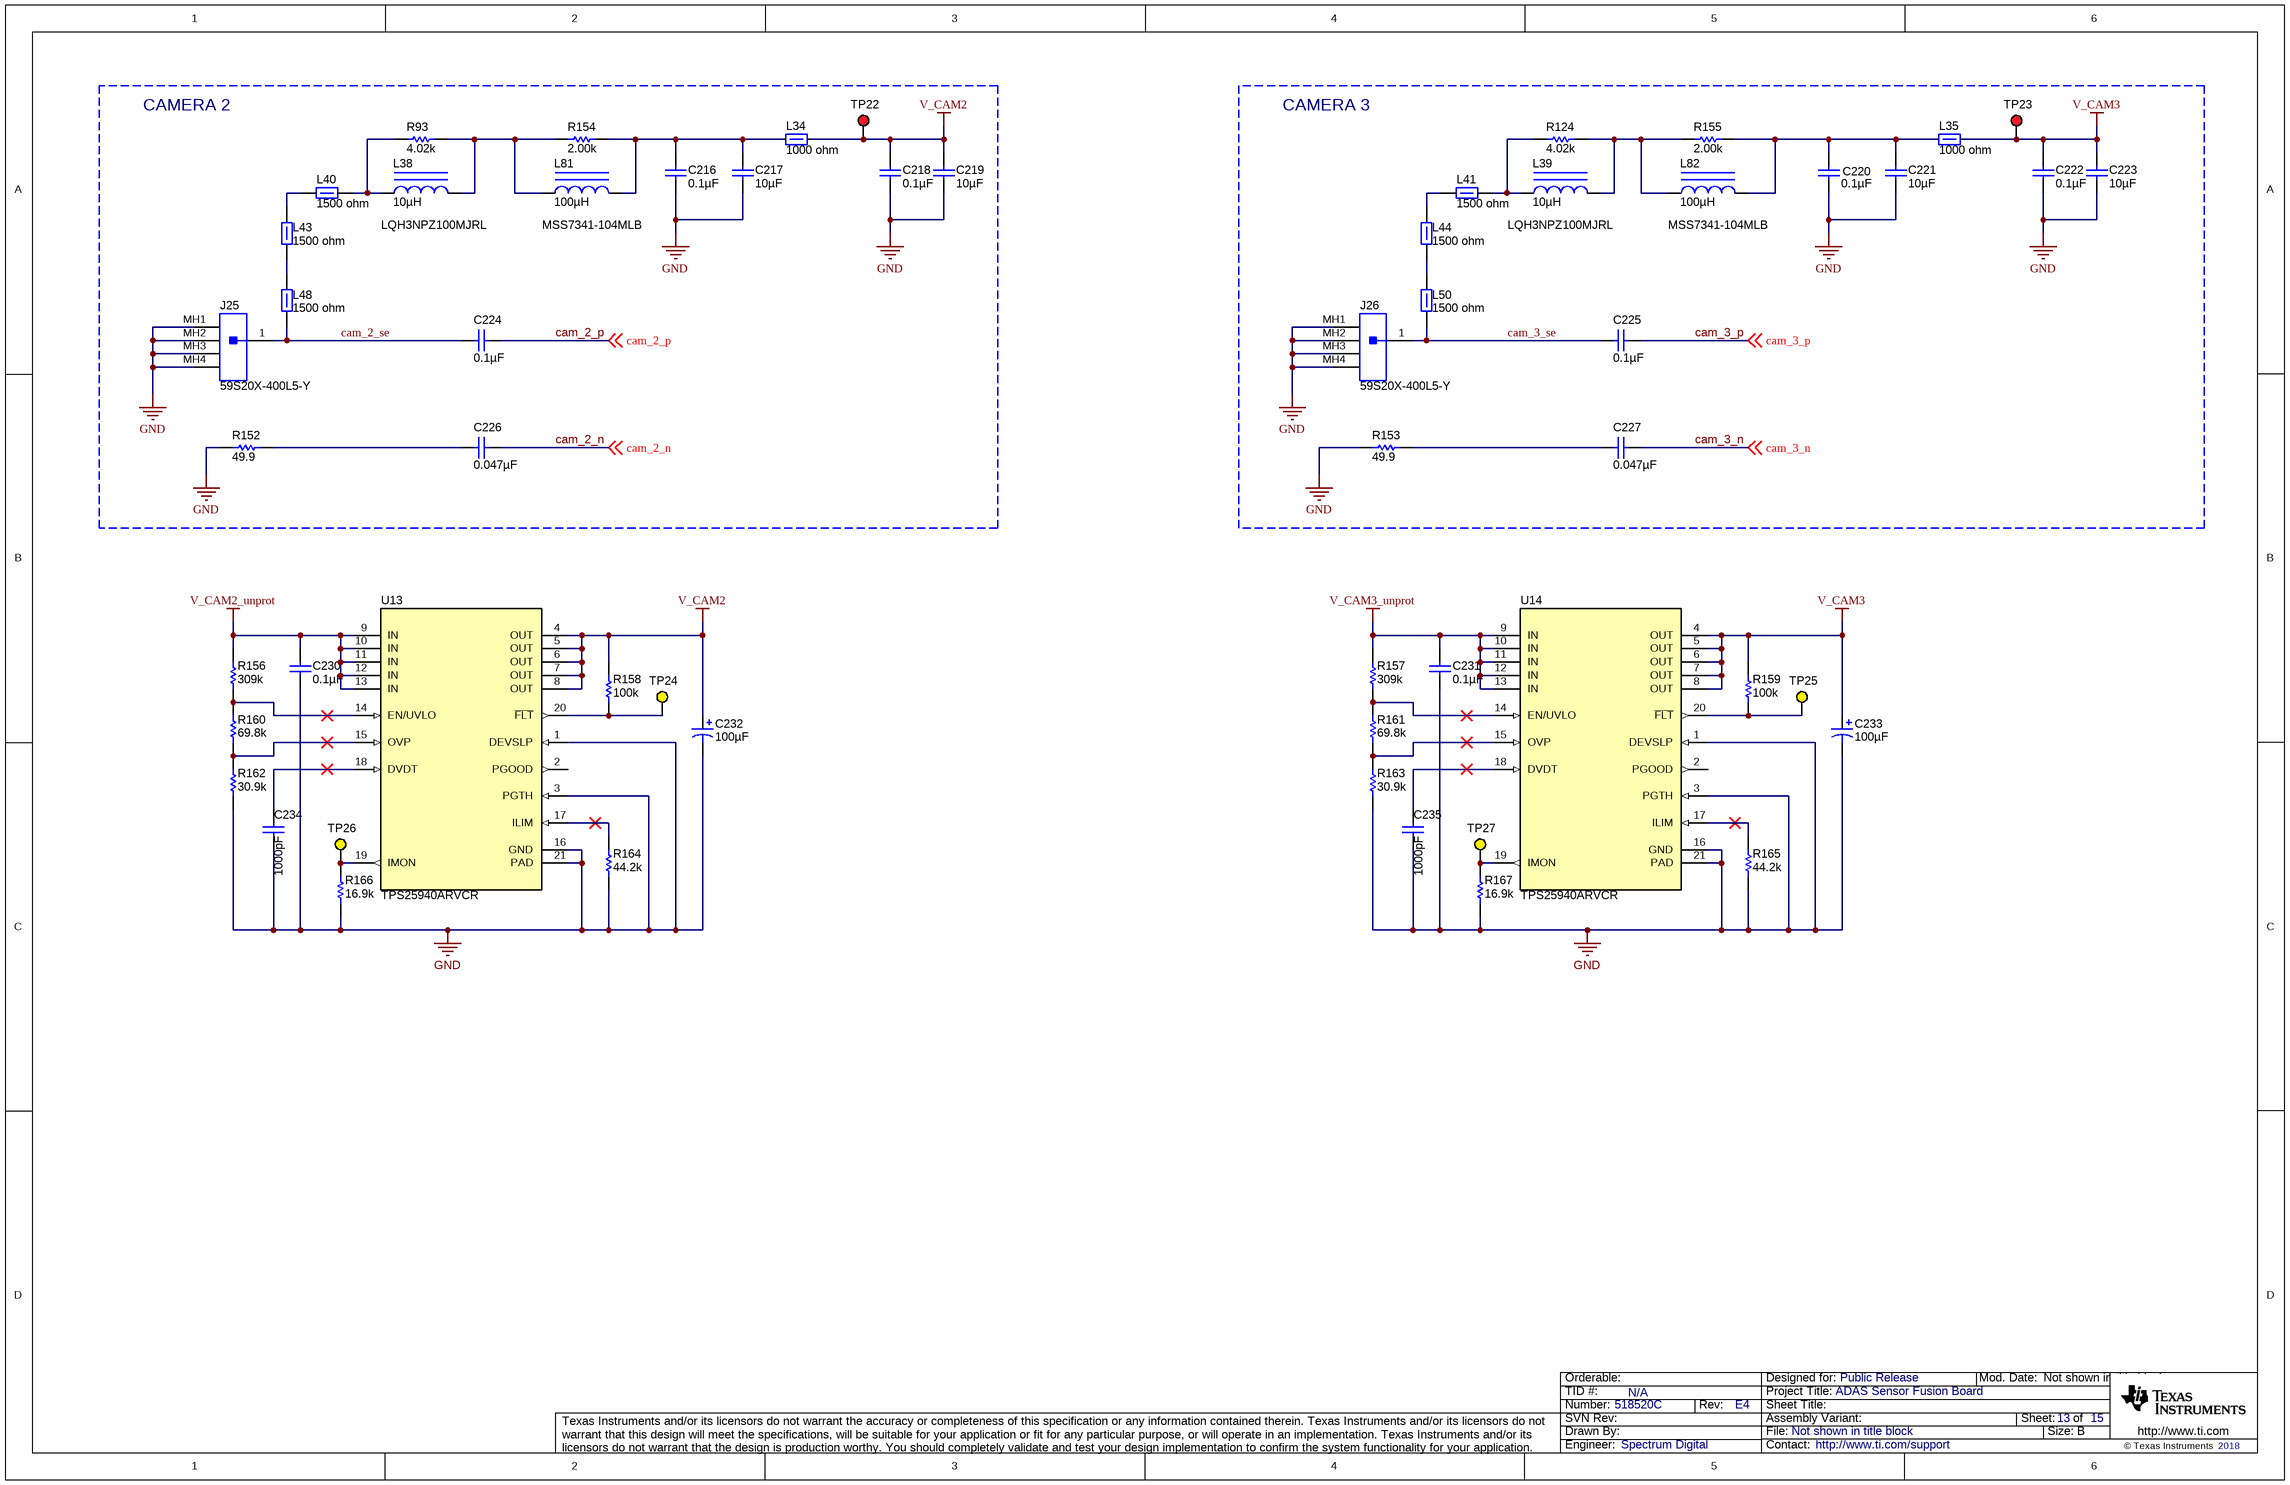
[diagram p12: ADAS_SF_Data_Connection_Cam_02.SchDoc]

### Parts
C216  ValueDisplayed: 0.1µF  [0402]  (hidden comment: GCM155R71H104KE02D)
C217  ValueDisplayed: 10µF  [0805_HV]  (hidden comment: TMK212BBJ106KG-T)
C218  ValueDisplayed: 0.1µF  [0402]  (hidden comment: GCM155R71H104KE02D)
C219  ValueDisplayed: 10µF  [0805_HV]  (hidden comment: TMK212BBJ106KG-T)
C220  ValueDisplayed: 0.1µF  [0402]  (hidden comment: GCM155R71H104KE02D)
C221  ValueDisplayed: 10µF  [0805_HV]  (hidden comment: TMK212BBJ106KG-T)
C222  ValueDisplayed: 0.1µF  [0402]  (hidden comment: GCM155R71H104KE02D)
C223  ValueDisplayed: 10µF  [0805_HV]  (hidden comment: TMK212BBJ106KG-T)
C224  ValueDisplayed: 0.1µF  [0402]  (hidden comment: GCM155R71H104KE02D)
C225  ValueDisplayed: 0.1µF  [0402]  (hidden comment: GCM155R71H104KE02D)
C226  ValueDisplayed: 0.047µF  [0402]  (hidden comment: CGA2B3X7R1H473K050BB)
C227  ValueDisplayed: 0.047µF  [0402]  (hidden comment: CGA2B3X7R1H473K050BB)
C230  ValueDisplayed: 0.1µF  [0603L]  (hidden comment: GRM188R72A104KA35D)
C231  ValueDisplayed: 0.1µF  [0603L]  (hidden comment: GRM188R72A104KA35D)
C232  ValueDisplayed: 100µF  [SM_RADIAL_E]  (hidden comment: EEE-FC1C101P)
C233  ValueDisplayed: 100µF  [SM_RADIAL_E]  (hidden comment: EEE-FC1C101P)
C234  ValueDisplayed: 1000pF  [0402]  (hidden comment: GCM155R71H102KA37D)
C235  ValueDisplayed: 1000pF  [0402]  (hidden comment: GCM155R71H102KA37D)
J25  59S20X-400L5-Y  [Rosenberger_59S20X-400L5]
J26  59S20X-400L5-Y  [Rosenberger_59S20X-400L5]
L34  value 1000 ohm  [0603]  (hidden comment: MPZ1608S102ATA00)
L35  value 1000 ohm  [0603]  (hidden comment: MPZ1608S102ATA00)
L38  LQH3NPZ100MJRL  ValueDisplayed: 10µH  [LQH3NPZ_JR]
L39  LQH3NPZ100MJRL  ValueDisplayed: 10µH  [LQH3NPZ_JR]
L40  ValueDisplayed: 1500 ohm  [0603]  (hidden comment: BLM18HE152SN1D)
L41  ValueDisplayed: 1500 ohm  [0603]  (hidden comment: BLM18HE152SN1D)
L43  ValueDisplayed: 1500 ohm  [0603]  (hidden comment: BLM18HE152SN1D)
L44  ValueDisplayed: 1500 ohm  [0603]  (hidden comment: BLM18HE152SN1D)
L48  ValueDisplayed: 1500 ohm  [0603]  (hidden comment: BLM18HE152SN1D)
L50  ValueDisplayed: 1500 ohm  [0603]  (hidden comment: BLM18HE152SN1D)
L81  MSS7341-104MLB  ValueDisplayed: 100µH  [MSS7341]
L82  MSS7341-104MLB  ValueDisplayed: 100µH  [MSS7341]
R93  ValueDisplayed: 4.02k  [0603]  (hidden comment: CRCW06034K02FKEA)
R124  ValueDisplayed: 4.02k  [0603]  (hidden comment: CRCW06034K02FKEA)
R152  ValueDisplayed: 49.9  [0402]  (hidden comment: CRCW040249R9FKED)
R153  ValueDisplayed: 49.9  [0402]  (hidden comment: CRCW040249R9FKED)
R154  ValueDisplayed: 2.00k  [0603]  (hidden comment: CRCW06032K00FKEA)
R155  ValueDisplayed: 2.00k  [0603]  (hidden comment: CRCW06032K00FKEA)
R156  ValueDisplayed: 309k  [0402]  (hidden comment: CRCW0402309KFKED)
R157  ValueDisplayed: 309k  [0402]  (hidden comment: CRCW0402309KFKED)
R158  ValueDisplayed: 100k  [0402]  (hidden comment: CRCW0402100KDHEDP)
R159  ValueDisplayed: 100k  [0402]  (hidden comment: CRCW0402100KDHEDP)
R160  ValueDisplayed: 69.8k  [0402]  (hidden comment: CRCW040269K8FKED)
R161  ValueDisplayed: 69.8k  [0402]  (hidden comment: CRCW040269K8FKED)
R162  ValueDisplayed: 30.9k  [0402]  (hidden comment: CRCW040230K9FKED)
R163  ValueDisplayed: 30.9k  [0402]  (hidden comment: CRCW040230K9FKED)
R164  ValueDisplayed: 44.2k  [0402]  (hidden comment: CRCW040244K2FKED)
R165  ValueDisplayed: 44.2k  [0402]  (hidden comment: CRCW040244K2FKED)
R166  ValueDisplayed: 16.9k  [0402]  (hidden comment: CRCW040216K9FKED)
R167  ValueDisplayed: 16.9k  [0402]  (hidden comment: CRCW040216K9FKED)
TP22  5000  [Keystone5000]  (value not drawn)
TP23  5000  [Keystone5000]  (value not drawn)
TP24  5004  [Keystone5004]  (value not drawn)
TP25  5004  [Keystone5004]  (value not drawn)
TP26  5004  [Keystone5004]  (value not drawn)
TP27  5004  [Keystone5004]  (value not drawn)
U13  TPS25940ARVCR  [RVC0020A]
U14  TPS25940ARVCR  [RVC0020A]

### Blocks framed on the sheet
CAMERA 2: C216-C219 C224 C226 J25 L34 L38 L40 L43 L48 L81 R93 R152 R154 TP22
CAMERA 3: C220-C223 C225 C227 J26 L35 L39 L41 L44 L50 L82 R124 R153 R155 TP23

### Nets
GND: C216.2 C217.2 C218.2 C219.2 C220.2 C221.2 C222.2 C223.2 C230.1 C231.1 C232.2(-) C233.2(-) C234.2 C235.2 J25.MH1 J25.MH2 J25.MH3 J25.MH4 J26.MH1 J26.MH2 J26.MH3 J26.MH4 R152.1 R153.1 R162.1 R163.1 R164.1 R165.1 R166.1 R167.1 U13.1(DEVSLP) U13.3(PGTH) U13.16(GND) U13.21(PAD) U14.1(DEVSLP) U14.3(PGTH) U14.16(GND) U14.21(PAD)
V_CAM2: C218.1 C219.1 C232.1(+) L34.2 R158.2 TP22.1 U13.4(OUT) U13.5(OUT) U13.6(OUT) U13.7(OUT) U13.8(OUT)
V_CAM2_unprot: C230.2 R156.2 U13.9(IN) U13.10(IN) U13.11(IN) U13.12(IN) U13.13(IN)
V_CAM3: C222.1 C223.1 C233.1(+) L35.2 R159.2 TP23.1 U14.4(OUT) U14.5(OUT) U14.6(OUT) U14.7(OUT) U14.8(OUT)
V_CAM3_unprot: C231.2 R157.2 U14.9(IN) U14.10(IN) U14.11(IN) U14.12(IN) U14.13(IN)
cam_2_n: C226.2 ; off-sheet cam_2_n
cam_2_p: C224.1 ; off-sheet cam_2_p
cam_2_se: C224.2 J25.1 L48.1
cam_3_n: C227.2 ; off-sheet cam_3_n
cam_3_p: C225.1 ; off-sheet cam_3_p
cam_3_se: C225.2 J26.1 L50.1
NetC216_1: C216.1 C217.1 L34.1 L81.2 R154.2
NetC220_1: C220.1 C221.1 L35.1 L82.2 R155.2
NetC226_1: C226.1 R152.2
NetC227_1: C227.1 R153.2
NetC234_1: C234.1 U13.18(DVDT)
NetC235_1: C235.1 U14.18(DVDT)
NetL38_1: L38.1 L40.2 R93.1
NetL38_2: L38.2 L81.1 R93.2 R154.1
NetL39_1: L39.1 L41.2 R124.1
NetL39_2: L39.2 L82.1 R124.2 R155.1
NetL40_1: L40.1 L43.2
NetL41_1: L41.1 L44.2
NetL43_1: L43.1 L48.2
NetL44_1: L44.1 L50.2
NetR156_1: R156.1 R160.2 U13.14(EN/UVLO)
NetR157_1: R157.1 R161.2 U14.14(EN/UVLO)
NetR158_1: R158.1 TP24.1 U13.20(~{FLT})
NetR159_1: R159.1 TP25.1 U14.20(~{FLT})
NetR160_1: R160.1 R162.2 U13.15(OVP)
NetR161_1: R161.1 R163.2 U14.15(OVP)
NetR164_2: R164.2 U13.17(ILIM)
NetR165_2: R165.2 U14.17(ILIM)
NetR166_2: R166.2 TP26.1 U13.19(IMON)
NetR167_2: R167.2 TP27.1 U14.19(IMON)

Not connected (* = marked no-connect by the designer): U13 2(PGOOD); U14 2(PGOOD)

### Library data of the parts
C216 C218 C220 C222 C224 C225 = GCM155R71H104KE02D: as C266 on sheet ADAS_SF_Data_Connection_Radar_02
C217 C219 C221 C223 = TMK212BBJ106KG-T: as C267 on sheet ADAS_SF_Data_Connection_Radar_02
C226 C227 = CGA2B3X7R1H473K050BB: as C279 on sheet ADAS_SF_Data_Connection_Radar_02
C230 C231 = GRM188R72A104KA35D: as C270 on sheet ADAS_SF_Data_Connection_Radar_02
C232 C233 = EEE-FC1C101P: as C272 on sheet ADAS_SF_Data_Connection_Radar_02
C234 C235 = GCM155R71H102KA37D: as C276 on sheet ADAS_SF_Data_Connection_Radar_02
J25 J26 = 59S20X-400L5-Y: as J32 on sheet ADAS_SF_Data_Connection_Radar_02
L34 L35 = MPZ1608S102ATA00: as L56 on sheet ADAS_SF_Data_Connection_Radar_02
L38 L39 = LQH3NPZ100MJRL: as L70 on sheet ADAS_SF_Data_Connection_Radar_02
L40 L41 L43 L44 L48 L50 = BLM18HE152SN1D: as L71-L73 on sheet ADAS_SF_Data_Connection_Radar_02
L81 L82 = MSS7341-104MLB: as L85 on sheet ADAS_SF_Data_Connection_Radar_02
R93 R124 = CRCW06034K02FKEA: as R127 on sheet ADAS_SF_Data_Connection_Radar_02
R152 R153 = CRCW040249R9FKED: as R212 on sheet ADAS_SF_Data_Connection_Radar_02
R154 R155 = CRCW06032K00FKEA: as R213 on sheet ADAS_SF_Data_Connection_Radar_02
R156 R157 = CRCW0402309KFKED: as R204 on sheet ADAS_SF_Data_Connection_Radar_02
R158 R159 = CRCW0402100KDHEDP: as R205 on sheet ADAS_SF_Data_Connection_Radar_02
R160 R161 = CRCW040269K8FKED: as R206 on sheet ADAS_SF_Data_Connection_Radar_02
R162 R163 = CRCW040230K9FKED: as R207 on sheet ADAS_SF_Data_Connection_Radar_02
R164 R165 = CRCW040244K2FKED: as R208 on sheet ADAS_SF_Data_Connection_Radar_02
R166 R167 = CRCW040216K9FKED: as R209 on sheet ADAS_SF_Data_Connection_Radar_02
TP22 TP23 = 5000: as TP34 on sheet ADAS_SF_Data_Connection_Radar_02
TP24-TP27 = 5004: as TP35 on sheet ADAS_SF_Data_Connection_Radar_02
U13 U14 = TPS25940ARVCR: as U19 on sheet ADAS_SF_Data_Connection_Radar_02

## Sheet ADAS_SF_Data_CSI2_Connector.SchDoc
size 431 x 279 mm; Date: Not shown in title block; ApprovedBy: Not shown in title block; CheckedBy: Not shown in title block; Author: Not shown in title block; CompanyName: Not shown in title block; Engineer: Not shown in title block; Organization: Not shown in title block; Address1: Not shown in title block; Address2: Not shown in title block; Address3: Not shown in title block; Address4: Not shown in title block; DocumentNumber: 1; Revision: Use project parameter SCH_Rev; SheetNumber: 14; SheetTotal: 15; PageSetup: Record=PageOptions¦CenterHorizontal=True¦CenterVertical=True¦PrintScale=1.00¦XCorrection=1.00¦YCorrection=1.00¦PrintKind=0¦BorderSize=5000000¦LeftOffset=0¦BottomOffset=0¦Orientation=2¦PaperLength=1000¦PaperWidth=1000¦Scale=100¦PaperSource=15¦PrintQuality=600¦MediaType=1¦DitherType=10¦PaperKind=Letter¦PrintScaleMode=1
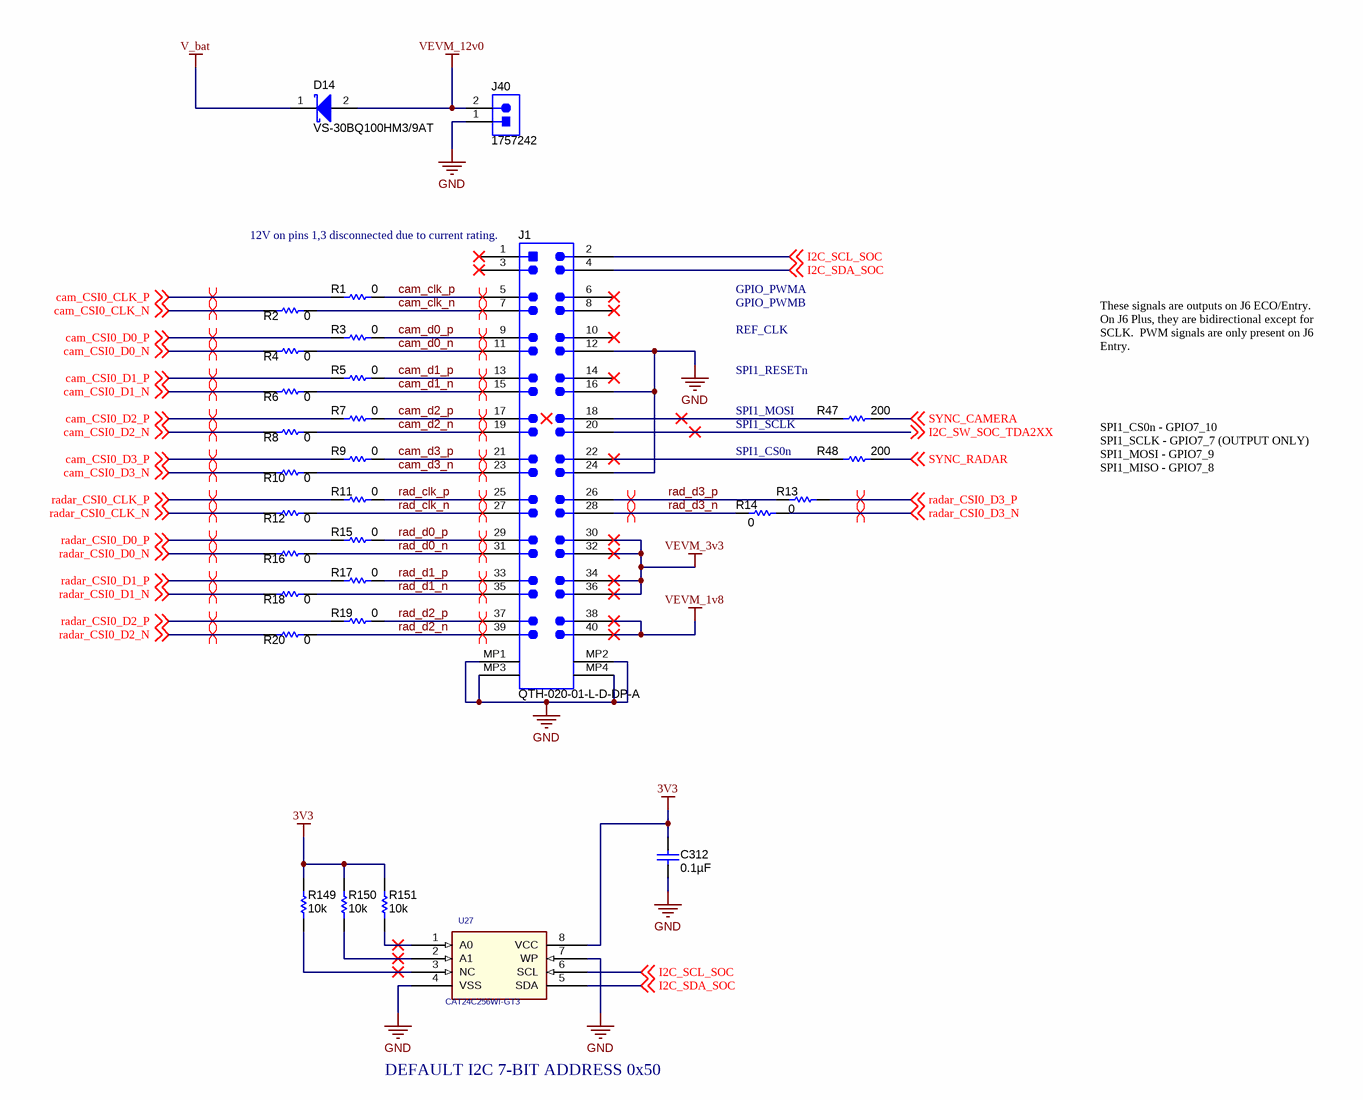
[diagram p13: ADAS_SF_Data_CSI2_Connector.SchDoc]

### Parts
C312  ValueDisplayed: 0.1µF  [0402]  (hidden comment: GCM155R71H104KE02D)
D14  VS-30BQ100HM3/9AT  [SMC]
J1  QTH-020-01-L-D-DP-A  [Samtec_QTH-020-01-L-D-DP-A]
J40  1757242  [PHOENIX_1757242]
R1  ValueDisplayed: 0  [0402]  (hidden comment: CRCW04020000Z0ED)
R2  ValueDisplayed: 0  [0402]  (hidden comment: CRCW04020000Z0ED)
R3  ValueDisplayed: 0  [0402]  (hidden comment: CRCW04020000Z0ED)
R4  ValueDisplayed: 0  [0402]  (hidden comment: CRCW04020000Z0ED)
R5  ValueDisplayed: 0  [0402]  (hidden comment: CRCW04020000Z0ED)
R6  ValueDisplayed: 0  [0402]  (hidden comment: CRCW04020000Z0ED)
R7  ValueDisplayed: 0  [0402]  (hidden comment: CRCW04020000Z0ED)
R8  ValueDisplayed: 0  [0402]  (hidden comment: CRCW04020000Z0ED)
R9  ValueDisplayed: 0  [0402]  (hidden comment: CRCW04020000Z0ED)
R10  ValueDisplayed: 0  [0402]  (hidden comment: CRCW04020000Z0ED)
R11  ValueDisplayed: 0  [0402]  (hidden comment: CRCW04020000Z0ED)
R12  ValueDisplayed: 0  [0402]  (hidden comment: CRCW04020000Z0ED)
R13  ValueDisplayed: 0  [0402]  (hidden comment: CRCW04020000Z0ED)
R14  ValueDisplayed: 0  [0402]  (hidden comment: CRCW04020000Z0ED)
R15  ValueDisplayed: 0  [0402]  (hidden comment: CRCW04020000Z0ED)
R16  ValueDisplayed: 0  [0402]  (hidden comment: CRCW04020000Z0ED)
R17  ValueDisplayed: 0  [0402]  (hidden comment: CRCW04020000Z0ED)
R18  ValueDisplayed: 0  [0402]  (hidden comment: CRCW04020000Z0ED)
R19  ValueDisplayed: 0  [0402]  (hidden comment: CRCW04020000Z0ED)
R20  ValueDisplayed: 0  [0402]  (hidden comment: CRCW04020000Z0ED)
R47  ValueDisplayed: 200  [0402]  (hidden comment: CRCW0402200RJNED)
R48  ValueDisplayed: 200  [0402]  (hidden comment: CRCW0402200RJNED)
R149  ValueDisplayed: 10k  [0402]  (hidden comment: CRCW040210K0JNED)
R150  ValueDisplayed: 10k  [0402]  (hidden comment: CRCW040210K0JNED)
R151  ValueDisplayed: 10k  [0402]  (hidden comment: CRCW040210K0JNED)
U27  CAT24C256WI-GT3  [so8-25x75-295]

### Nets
3V3: C312.1 R149.2 R150.2 R151.2 U27.8(VCC)
GND: C312.2 J1.12 J1.16 J1.24 J1.MP1 J1.MP2 J1.MP3 J1.MP4 J40.1 U27.4(VSS) U27.7(WP)
V_bat: D14.1(K)
VEVM_1v8: J1.38 J1.40
VEVM_3v3: J1.30 J1.32 J1.34 J1.36
VEVM_12v0: D14.2(A) J40.2
cam_clk_n: J1.7 R2.1
cam_clk_p: J1.5 R1.2
cam_CSI0_CLK_N: R2.2 ; off-sheet cam_CSI0_CLK_N
cam_CSI0_CLK_P: R1.1 ; off-sheet cam_CSI0_CLK_P
cam_CSI0_D0_N: R4.2 ; off-sheet cam_CSI0_D0_N
cam_CSI0_D0_P: R3.1 ; off-sheet cam_CSI0_D0_P
cam_CSI0_D1_N: R6.2 ; off-sheet cam_CSI0_D1_N
cam_CSI0_D1_P: R5.1 ; off-sheet cam_CSI0_D1_P
cam_CSI0_D2_N: R8.2 ; off-sheet cam_CSI0_D2_N
cam_CSI0_D2_P: R7.1 ; off-sheet cam_CSI0_D2_P
cam_CSI0_D3_N: R10.2 ; off-sheet cam_CSI0_D3_N
cam_CSI0_D3_P: R9.1 ; off-sheet cam_CSI0_D3_P
cam_d0_n: J1.11 R4.1
cam_d0_p: J1.9 R3.2
cam_d1_n: J1.15 R6.1
cam_d1_p: J1.13 R5.2
cam_d2_n: J1.19 R8.1
cam_d2_p: J1.17 R7.2
cam_d3_n: J1.23 R10.1
cam_d3_p: J1.21 R9.2
I2C_SCL_SOC: J1.2 U27.6(SCL) ; off-sheet I2C_SCL_SOC
I2C_SDA_SOC: J1.4 U27.5(SDA) ; off-sheet I2C_SDA_SOC
I2C_SW_SOC_TDA2XX: J1.20 ; off-sheet I2C_SW_SOC_TDA2XX
rad_clk_n: J1.27 R12.1
rad_clk_p: J1.25 R11.2
rad_d0_n: J1.31 R16.1
rad_d0_p: J1.29 R15.2
rad_d1_n: J1.35 R18.1
rad_d1_p: J1.33 R17.2
rad_d2_n: J1.39 R20.1
rad_d2_p: J1.37 R19.2
rad_d3_n: J1.28 R14.2
rad_d3_p: J1.26 R13.1
radar_CSI0_CLK_N: R12.2 ; off-sheet radar_CSI0_CLK_N
radar_CSI0_CLK_P: R11.1 ; off-sheet radar_CSI0_CLK_P
radar_CSI0_D0_N: R16.2 ; off-sheet radar_CSI0_D0_N
radar_CSI0_D0_P: R15.1 ; off-sheet radar_CSI0_D0_P
radar_CSI0_D1_N: R18.2 ; off-sheet radar_CSI0_D1_N
radar_CSI0_D1_P: R17.1 ; off-sheet radar_CSI0_D1_P
radar_CSI0_D2_N: R20.2 ; off-sheet radar_CSI0_D2_N
radar_CSI0_D2_P: R19.1 ; off-sheet radar_CSI0_D2_P
radar_CSI0_D3_N: R14.1 ; off-sheet radar_CSI0_D3_N
radar_CSI0_D3_P: R13.2 ; off-sheet radar_CSI0_D3_P
SYNC_CAMERA: R47.2 ; off-sheet SYNC_CAMERA
SYNC_RADAR: R48.2 ; off-sheet SYNC_RADAR
NetJ1_18: J1.18 R47.1
NetJ1_22: J1.22 R48.1
NetR149_1: R149.1 U27.3(NC)
NetR150_1: R150.1 U27.2(A1)
NetR151_1: R151.1 U27.1(A0)

Not connected (* = marked no-connect by the designer): J1 1* 3* 6* 8* 10* 14*

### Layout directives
differential pair: cam_clk_n, cam_clk_p, cam_CSI0_CLK_N, cam_CSI0_CLK_P, cam_CSI0_D0_N, cam_CSI0_D0_P, cam_CSI0_D1_N, cam_CSI0_D1_P, cam_CSI0_D2_N, cam_CSI0_D2_P, cam_CSI0_D3_N, cam_CSI0_D3_P, cam_d0_n, cam_d0_p, cam_d1_n, cam_d1_p, cam_d2_n, cam_d2_p, cam_d3_n, cam_d3_p, rad_clk_n, rad_clk_p, rad_d0_n, rad_d0_p, rad_d1_n, rad_d1_p, rad_d2_n, rad_d2_p, rad_d3_n, rad_d3_p, radar_CSI0_CLK_N, radar_CSI0_CLK_P, radar_CSI0_D0_N, radar_CSI0_D0_P, radar_CSI0_D1_N, radar_CSI0_D1_P, radar_CSI0_D2_N, radar_CSI0_D2_P, radar_CSI0_D3_N, radar_CSI0_D3_P

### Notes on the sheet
- (near J1) 12V on pins 1,3 disconnected due to current rating.
- GPIO_PWMB
- GPIO_PWMA
- SPI1_RESETn
- REF_CLK
- These signals are outputs on J6 ECO/Entry.
  On J6 Plus, they are bidirectional except for SCLK.  PWM signals are only present on J6 Entry.
- SPI1_CS0n
- SPI1_SCLK
- SPI1_MOSI
- SPI1_CS0n - GPIO7_10
  SPI1_SCLK - GPIO7_7 (OUTPUT ONLY)
  SPI1_MOSI - GPIO7_9
  SPI1_MISO - GPIO7_8
- DEFAULT I2C 7-BIT ADDRESS 0x50

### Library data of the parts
C312 = GCM155R71H104KE02D: CAP, CERM, 0.1 µF, 50 V, +/- 10%, X7R, AEC-Q200 Grade 1, 0402; Manufacturer: MuRata; Polarized: N; CompType: Capacitor; Value: 0.1uF; U/M: EA; Cap_F: 0.0000001; Tolerance_%: 10; Value1: Unknown; VDC_V: 50; Value2: 50V; TaMin_C: -55; TaMax_C: 125; AEC Category: Q200; AEC Qualified: Y; AEC Grade: 1; SizeArea_mm2: 0.5; SizeAreaWB_mm2: 3; SizeZ_mm: 0.6
D14 = VS-30BQ100HM3/9AT: Diode, Schottky, 100 V, 3 A, AEC-Q101, SMC; Manufacturer: Vishay-Semiconductor; U/M: EA; Vf_V: 0.79; Value: 100V; Value1: 3A; Value2: 0.79V; Io_A: 3; Vr_V: 100; TJmax_C: 175; SizeAreaWB_mm2: 83.2686; SizeArea_mm2: 50.5686; SizeX_mm: 8.13; SizeY_mm: 6.22; SizeZ_mm: 2.6; AEC Category: Q101; AEC Qualified: Y
J1 = QTH-020-01-L-D-DP-A: Male, Differential, 0.5mm, 10 pair x2, Gold, SMT; Manufacturer: Samtec; SymbolCreator: a0411947; CompType: Connector
J40 = 1757242: Header (Shrouded), 5.08 mm, 2x1, Tin, R/A, TH; Manufacturer: Phoenix Contact; SymbolCreator: a0412235
R1-R20 = CRCW04020000Z0ED: RES, 0, 5%, 0.063 W, 0402; Manufacturer: Vishay-Dale; CompType: Resistor; Value: 0; Value_Code: 0000; Tolerance_%: 5; Power_W: 0.063; Value2: 0.063W; VDC_V: 50; TempCo: 200 ppm/C; EIA_Code: E24; U/M: EA; AEC Category: Q200
R47 R48 = CRCW0402200RJNED: RES, 200, 5%, 0.063 W, 0402; Manufacturer: Vishay-Dale; CompType: Resistor; Value: 200; Value_Code: 200R; Tolerance_%: 5; Power_W: 0.063; Value2: 0.063W; VDC_V: 50; TempCo: 200 ppm/C; EIA_Code: E24; U/M: EA; AEC Category: Q200; SizeArea_mm2: 0.5; SizeX_mm: 1; SizeZ_mm: 0.6
R149-R151 = CRCW040210K0JNED: RES, 10 k, 5%, 0.063 W, 0402; Manufacturer: Vishay-Dale; CompType: Resistor; Value: 10k; Res_ohm: 10000; Value_Code: 10k0; Tolerance_%: 5; Power_W: 0.063; Value2: 0.063W; VDC_V: 50; TempCo: 200 ppm/C; EIA_Code: E24; U/M: EA; AEC Category: Q200
U27 = 24WC256: Part #: 102235-0001R; Manufacturer: Catalyst Semiconductor

## Sheet ADAS_SF_rev1_Hardware.SchDoc
size 431 x 279 mm; Date: Not shown in title block; ApprovedBy: Not shown in title block; CheckedBy: Not shown in title block; Author: Not shown in title block; CompanyName: Not shown in title block; Engineer: Not shown in title block; Organization: Not shown in title block; Address1: Not shown in title block; Address2: Not shown in title block; Address3: Not shown in title block; Address4: Not shown in title block; DocumentNumber: 1; Revision: Use project parameter SCH_Rev; SheetNumber: 15; SheetTotal: 15; PageSetup: Record=PageOptions¦CenterHorizontal=True¦CenterVertical=True¦PrintScale=1.00¦XCorrection=1.00¦YCorrection=1.00¦PrintKind=0¦BorderSize=5000000¦LeftOffset=0¦BottomOffset=0¦Orientation=2¦PaperLength=1000¦PaperWidth=1000¦Scale=100¦PaperSource=15¦PrintQuality=600¦MediaType=1¦DitherType=10¦PaperKind=Letter¦PrintScaleMode=1
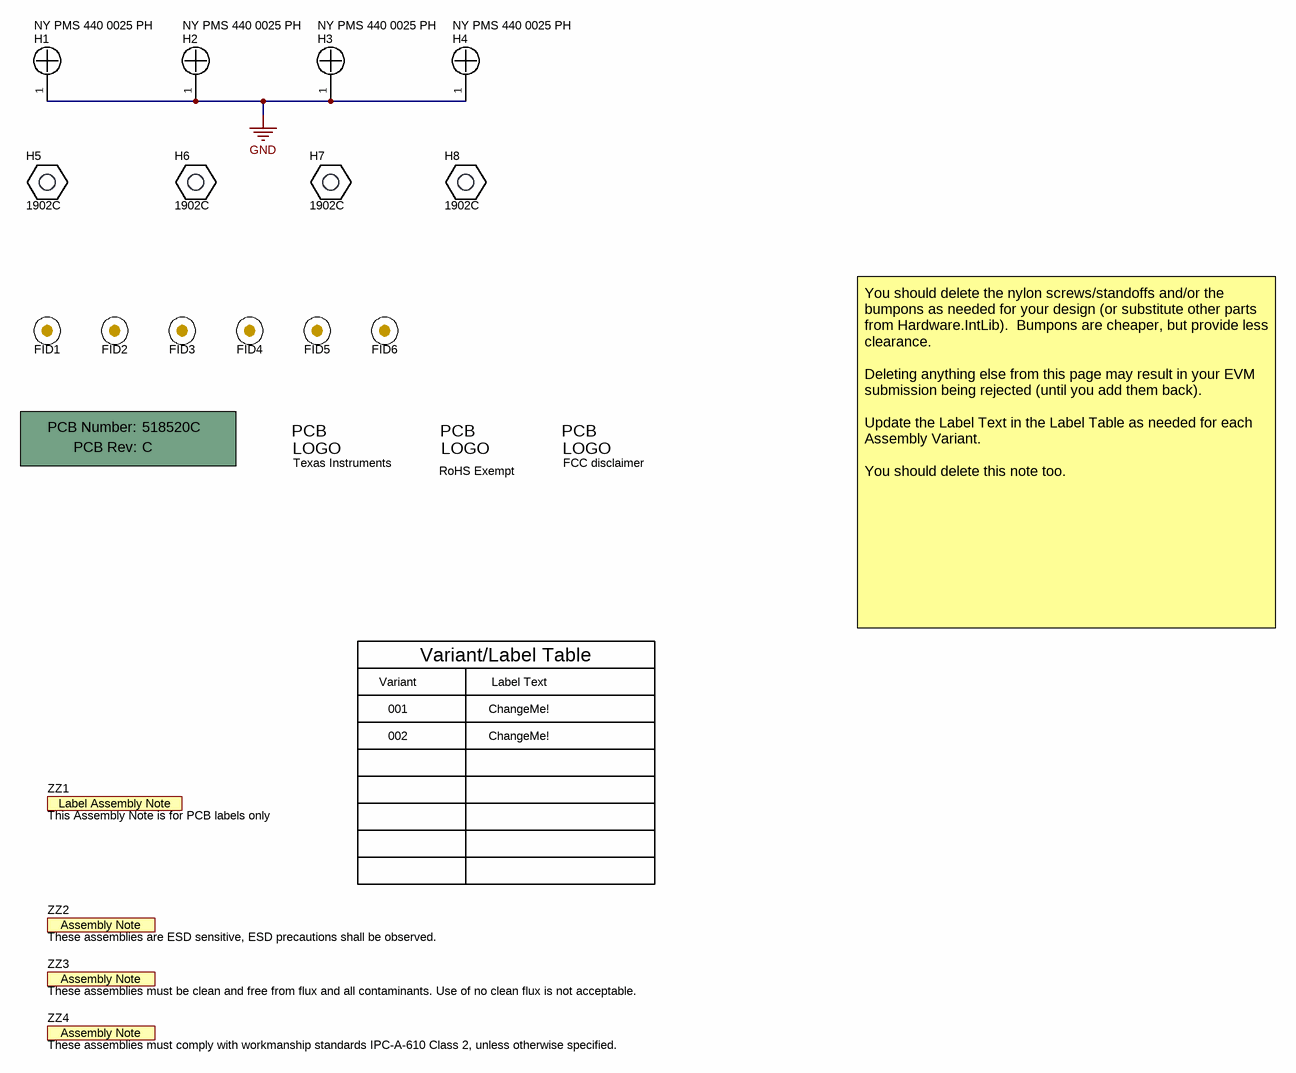
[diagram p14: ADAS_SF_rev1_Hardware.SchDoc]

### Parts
!PCB  Printed Circuit Board  (value not drawn)  (mechanical)
FID1  Fiducial  [Fiducial10-20]  (value not drawn)
FID2  Fiducial  [Fiducial10-20]  (value not drawn)
FID3  Fiducial  [Fiducial10-20]  (value not drawn)
FID4  Fiducial  [Fiducial10-20]  (value not drawn)
FID5  Fiducial  [Fiducial10-20]  (value not drawn)
FID6  Fiducial  [Fiducial10-20]  (value not drawn)
H1  NY PMS 440 0025 PH  [NY PMS 440 0025 PH]
H2  NY PMS 440 0025 PH  [NY PMS 440 0025 PH]
H3  NY PMS 440 0025 PH  [NY PMS 440 0025 PH]
H4  NY PMS 440 0025 PH  [NY PMS 440 0025 PH]
H5  1902C  [Keystone_1902C]
H6  1902C  [Keystone_1902C]
H7  1902C  [Keystone_1902C]
H8  1902C  [Keystone_1902C]
Logo1  Texas Instruments  [TI_Stacked_Overlay_Small]  (no BOM)
Logo2  RoHS Exempt  [RoHS_Exempt]  (no BOM)
Logo3  FCC disclaimer  [FCC_disclaimer]  (no BOM)
ZZ1  This Assembly Note is for PCB labels only  [AssemblyNoteLabel]  (no BOM)
ZZ2  These assemblies are ESD sensitive, ESD precautions shall be observed.  [AssemblyNote]  (no BOM)
ZZ3  These assemblies must be clean and free from flux and all contaminants. Use of no clean flux is not acceptable.  [AssemblyNote]  (no BOM)
ZZ4  These assemblies must comply with workmanship standards IPC-A-610 Class 2, unless otherwise specified.  [AssemblyNote]  (no BOM)

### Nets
GND: H1.1 H2.1 H3.1 H4.1

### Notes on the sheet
- Variant
- Variant/Label Table
- Label Text
- You should delete the nylon screws/standoffs and/or the bumpons as needed for your design (or substitute other parts from Hardware.IntLib).  Bumpons are cheaper, but provide less clearance.
  Deleting anything else from this page may result in your EVM submission being rejected (until you add them back).
  Update the Label Text in the Label Table as needed for each Assembly Variant.
  You should delete this note too.
- 001
- 002
- ChangeMe!

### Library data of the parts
!PCB = PCB: Manufacturer: Any; PartNumber: 518520C; SymbolCreator: a0412235
FID1-FID6 = Fiducial: Fiducial mark.  There is nothing to buy or mount.; SymbolCreator: codlsc
H1-H4 = NY PMS 440 0025 PH: Machine Screw, Round, #4-40 x 1/4, Nylon, Philips panhead; Manufacturer: B&F Fastener Supply; CompType: Hardware; SymbolCreator: codlsc; U/M: EA
H5-H8 = 1902C: Standoff, Hex, 0.5"L #4-40 Nylon; Manufacturer: Keystone; CompType: Hardware
Logo1 = TI_Logo: Texas Instrument Corporate Signature; SymbolCreator: codlsc
Logo2 = RoHS_Exempt: SymbolCreator: a0412235
Logo3 = FCC_disclaimer: SymbolCreator: codlsc
ZZ1 = AssemblyNoteLabel: SymbolCreator: a0412235
ZZ2-ZZ4 = AssemblyNote: SymbolCreator: codlsc

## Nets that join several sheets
1V1: ADAS_SF_Power_Buck_3V3_1V8_1V1 (J20.2 R215.2 TP50.1), ADAS_SF_Data_Deserializer_Camera (6 pins), ADAS_SF_Data_Deserializer_Radar (6 pins)
1V8: ADAS_SF_Power_Buck_3V3_1V8_1V1 (D6.1 J19.2 R214.2 TP48.1), ADAS_SF_Data_Deserializer_Camera (15 pins), ADAS_SF_Data_Deserializer_Radar (15 pins)
3V3: ADAS_SF_Power_Buck_3V3_1V8_1V1 (5 pins), ADAS_SF_Data_MSP430 (29 pins), ADAS_SF_Data_Deserializer_Camera (C57.1 L10.1 R26.2 R186.2), ADAS_SF_Data_Deserializer_Radar (5 pins), ADAS_SF_Data_Radar_Mux (24 pins), ADAS_SF_Data_CSI2_Connector (5 pins)
5V: ADAS_SF_Power_Buck_5V (D10.1 J21.2 R253.2 TP46.1), ADAS_SF_Power_Boost_12V (8 pins), ADAS_SF_Power_Buck_3V3_1V8_1V1 (J17.1 R200.1), ADAS_SF_Data_Connection_Radar_01 (J27.1), ADAS_SF_Data_Connection_Cam_01 (J22.1)
12V: ADAS_SF_Power_Boost_12V (J16.2 R187.2 TP47.1), ADAS_SF_Data_Connection_Radar_01 (J27.3), ADAS_SF_Data_Connection_Cam_01 (J22.3)
GND: ADAS_SF_Power_Battery_Input (17 pins), ADAS_SF_Power_Buck_5V (30 pins), ADAS_SF_Power_Boost_12V (20 pins), ADAS_SF_Power_Buck_3V3_1V8_1V1 (32 pins), ADAS_SF_Data_MSP430 (38 pins), ADAS_SF_Data_Deserializer_Camera (64 pins), ADAS_SF_Data_Deserializer_Radar (66 pins), ADAS_SF_Data_Radar_Mux (44 pins), ADAS_SF_Data_Connection_Radar_01 (48 pins), ADAS_SF_Data_Connection_Radar_02 (48 pins), ADAS_SF_Data_Connection_Cam_01 (38 pins), ADAS_SF_Data_Connection_Cam_02 (38 pins), ADAS_SF_Data_CSI2_Connector (11 pins), ADAS_SF_rev1_Hardware (H1.1 H2.1 H3.1 H4.1)
V_bat: ADAS_SF_Power_Battery_Input (6 pins), ADAS_SF_Data_CSI2_Connector (D14.1)
V_CAM2_unprot: ADAS_SF_Data_Connection_Cam_01 (R130.1), ADAS_SF_Data_Connection_Cam_02 (7 pins)
V_CAM3_unprot: ADAS_SF_Data_Connection_Cam_01 (R131.1), ADAS_SF_Data_Connection_Cam_02 (7 pins)
V_RADAR2_unprot: ADAS_SF_Data_Connection_Radar_01 (R170.1), ADAS_SF_Data_Connection_Radar_02 (7 pins)
V_RADAR3_unprot: ADAS_SF_Data_Connection_Radar_01 (R171.1), ADAS_SF_Data_Connection_Radar_02 (7 pins)
Vin_protect: ADAS_SF_Power_Battery_Input (J13.2 R172.2 TP51.1), ADAS_SF_Power_Buck_5V (7 pins)
cam_0_n: ADAS_SF_Data_Deserializer_Camera (U1.51), ADAS_SF_Data_Connection_Cam_01 (C206.2)
cam_0_p: ADAS_SF_Data_Deserializer_Camera (U1.50), ADAS_SF_Data_Connection_Cam_01 (C204.1)
cam_1_n: ADAS_SF_Data_Deserializer_Camera (U1.54), ADAS_SF_Data_Connection_Cam_01 (C207.2)
cam_1_p: ADAS_SF_Data_Deserializer_Camera (U1.53), ADAS_SF_Data_Connection_Cam_01 (C205.1)
cam_2_n: ADAS_SF_Data_Deserializer_Camera (U1.60), ADAS_SF_Data_Connection_Cam_02 (C226.2)
cam_2_p: ADAS_SF_Data_Deserializer_Camera (U1.59), ADAS_SF_Data_Connection_Cam_02 (C224.1)
cam_3_n: ADAS_SF_Data_Deserializer_Camera (U1.63), ADAS_SF_Data_Connection_Cam_02 (C227.2)
cam_3_p: ADAS_SF_Data_Deserializer_Camera (U1.62), ADAS_SF_Data_Connection_Cam_02 (C225.1)
cam_CSI0_CLK_N: ADAS_SF_Data_Deserializer_Camera (U1.22), ADAS_SF_Data_CSI2_Connector (R2.2)
cam_CSI0_CLK_P: ADAS_SF_Data_Deserializer_Camera (U1.23), ADAS_SF_Data_CSI2_Connector (R1.1)
cam_CSI0_D0_N: ADAS_SF_Data_Deserializer_Camera (U1.24), ADAS_SF_Data_CSI2_Connector (R4.2)
cam_CSI0_D0_P: ADAS_SF_Data_Deserializer_Camera (U1.25), ADAS_SF_Data_CSI2_Connector (R3.1)
cam_CSI0_D1_N: ADAS_SF_Data_Deserializer_Camera (U1.26), ADAS_SF_Data_CSI2_Connector (R6.2)
cam_CSI0_D1_P: ADAS_SF_Data_Deserializer_Camera (U1.27), ADAS_SF_Data_CSI2_Connector (R5.1)
cam_CSI0_D2_N: ADAS_SF_Data_Deserializer_Camera (U1.28), ADAS_SF_Data_CSI2_Connector (R8.2)
cam_CSI0_D2_P: ADAS_SF_Data_Deserializer_Camera (U1.29), ADAS_SF_Data_CSI2_Connector (R7.1)
cam_CSI0_D3_N: ADAS_SF_Data_Deserializer_Camera (U1.30), ADAS_SF_Data_CSI2_Connector (R10.2)
cam_CSI0_D3_P: ADAS_SF_Data_Deserializer_Camera (U1.31), ADAS_SF_Data_CSI2_Connector (R9.1)
GPIO0_0: ADAS_SF_Data_MSP430 (U3.17), ADAS_SF_Data_Deserializer_Radar (U2.9)
GPIO0_1: ADAS_SF_Data_MSP430 (U3.18), ADAS_SF_Data_Deserializer_Radar (U2.10)
GPIO0_2: ADAS_SF_Data_MSP430 (U3.19), ADAS_SF_Data_Deserializer_Radar (U2.14)
GPIO0_3: ADAS_SF_Data_MSP430 (U3.20), ADAS_SF_Data_Deserializer_Radar (U2.15)
GPIO1_0: ADAS_SF_Data_MSP430 (U3.21), ADAS_SF_Data_Deserializer_Camera (U1.9)
GPIO1_1: ADAS_SF_Data_MSP430 (U3.22), ADAS_SF_Data_Deserializer_Camera (U1.10)
GPIO1_2: ADAS_SF_Data_MSP430 (U3.23), ADAS_SF_Data_Deserializer_Camera (U1.14)
GPIO1_3: ADAS_SF_Data_MSP430 (U3.24), ADAS_SF_Data_Deserializer_Camera (U1.15)
I2C_SCL_SOC: ADAS_SF_Data_MSP430 (J7.2 R56.1 U4.3), ADAS_SF_Data_CSI2_Connector (J1.2 U27.6)
I2C_SCL_UB960: ADAS_SF_Data_MSP430 (R67.1 U5.3), ADAS_SF_Data_Deserializer_Camera (U1.12), ADAS_SF_Data_Deserializer_Radar (U2.12)
I2C_SDA_SOC: ADAS_SF_Data_MSP430 (J7.3 R57.1 U4.4), ADAS_SF_Data_CSI2_Connector (J1.4 U27.5)
I2C_SDA_UB960: ADAS_SF_Data_MSP430 (R68.1 U5.4), ADAS_SF_Data_Deserializer_Camera (U1.11), ADAS_SF_Data_Deserializer_Radar (U2.11)
I2C_SW_SOC_TDA2XX: ADAS_SF_Data_MSP430 (R50.2), ADAS_SF_Data_CSI2_Connector (J1.20)
INTB_CAM: ADAS_SF_Data_MSP430 (U3.32), ADAS_SF_Data_Deserializer_Camera (R186.1 U1.6)
INTB_RADAR: ADAS_SF_Data_MSP430 (U3.31), ADAS_SF_Data_Deserializer_Radar (R245.1 U2.6)
PDB_UB960_cam: ADAS_SF_Data_MSP430 (U3.14), ADAS_SF_Data_Deserializer_Camera (R22.2)
PDB_UB960_radar: ADAS_SF_Data_MSP430 (U3.25), ADAS_SF_Data_Deserializer_Radar (R35.2)
radar_0_coax_n: ADAS_SF_Data_Radar_Mux (U23.12), ADAS_SF_Data_Connection_Radar_01 (C249.2)
radar_0_coax_p: ADAS_SF_Data_Radar_Mux (U23.13), ADAS_SF_Data_Connection_Radar_01 (C245.1)
radar_0_HSD_n: ADAS_SF_Data_Radar_Mux (U23.9), ADAS_SF_Data_Connection_Radar_01 (C241.2)
radar_0_HSD_p: ADAS_SF_Data_Radar_Mux (U23.10), ADAS_SF_Data_Connection_Radar_01 (C244.2)
radar_0_n: ADAS_SF_Data_Deserializer_Radar (U2.51), ADAS_SF_Data_Radar_Mux (U23.3)
radar_0_p: ADAS_SF_Data_Deserializer_Radar (U2.50), ADAS_SF_Data_Radar_Mux (U23.2)
radar_1_coax_n: ADAS_SF_Data_Radar_Mux (U24.12), ADAS_SF_Data_Connection_Radar_01 (C264.2)
radar_1_coax_p: ADAS_SF_Data_Radar_Mux (U24.13), ADAS_SF_Data_Connection_Radar_01 (C260.1)
radar_1_HSD_n: ADAS_SF_Data_Radar_Mux (U24.9), ADAS_SF_Data_Connection_Radar_01 (C256.2)
radar_1_HSD_p: ADAS_SF_Data_Radar_Mux (U24.10), ADAS_SF_Data_Connection_Radar_01 (C259.2)
radar_1_n: ADAS_SF_Data_Deserializer_Radar (U2.54), ADAS_SF_Data_Radar_Mux (U24.3)
radar_1_p: ADAS_SF_Data_Deserializer_Radar (U2.53), ADAS_SF_Data_Radar_Mux (U24.2)
radar_2_coax_n: ADAS_SF_Data_Radar_Mux (U25.12), ADAS_SF_Data_Connection_Radar_02 (C279.2)
radar_2_coax_p: ADAS_SF_Data_Radar_Mux (U25.13), ADAS_SF_Data_Connection_Radar_02 (C275.1)
radar_2_HSD_n: ADAS_SF_Data_Radar_Mux (U25.9), ADAS_SF_Data_Connection_Radar_02 (C271.2)
radar_2_HSD_p: ADAS_SF_Data_Radar_Mux (U25.10), ADAS_SF_Data_Connection_Radar_02 (C274.2)
radar_2_n: ADAS_SF_Data_Deserializer_Radar (U2.60), ADAS_SF_Data_Radar_Mux (U25.3)
radar_2_p: ADAS_SF_Data_Deserializer_Radar (U2.59), ADAS_SF_Data_Radar_Mux (U25.2)
radar_3_coax_n: ADAS_SF_Data_Radar_Mux (U26.12), ADAS_SF_Data_Connection_Radar_02 (C294.2)
radar_3_coax_p: ADAS_SF_Data_Radar_Mux (U26.13), ADAS_SF_Data_Connection_Radar_02 (C290.1)
radar_3_HSD_n: ADAS_SF_Data_Radar_Mux (U26.9), ADAS_SF_Data_Connection_Radar_02 (C286.2)
radar_3_HSD_p: ADAS_SF_Data_Radar_Mux (U26.10), ADAS_SF_Data_Connection_Radar_02 (C289.2)
radar_3_n: ADAS_SF_Data_Deserializer_Radar (U2.63), ADAS_SF_Data_Radar_Mux (U26.3)
radar_3_p: ADAS_SF_Data_Deserializer_Radar (U2.62), ADAS_SF_Data_Radar_Mux (U26.2)
RADAR_COAX_SEL: ADAS_SF_Data_MSP430 (R233.2 S3.3), ADAS_SF_Data_Radar_Mux (U23.7 U24.7 U25.7 U26.7)
radar_CSI0_CLK_N: ADAS_SF_Data_Deserializer_Radar (U2.22), ADAS_SF_Data_CSI2_Connector (R12.2)
radar_CSI0_CLK_P: ADAS_SF_Data_Deserializer_Radar (U2.23), ADAS_SF_Data_CSI2_Connector (R11.1)
radar_CSI0_D0_N: ADAS_SF_Data_Deserializer_Radar (U2.24), ADAS_SF_Data_CSI2_Connector (R16.2)
radar_CSI0_D0_P: ADAS_SF_Data_Deserializer_Radar (U2.25), ADAS_SF_Data_CSI2_Connector (R15.1)
radar_CSI0_D1_N: ADAS_SF_Data_Deserializer_Radar (U2.26), ADAS_SF_Data_CSI2_Connector (R18.2)
radar_CSI0_D1_P: ADAS_SF_Data_Deserializer_Radar (U2.27), ADAS_SF_Data_CSI2_Connector (R17.1)
radar_CSI0_D2_N: ADAS_SF_Data_Deserializer_Radar (U2.28), ADAS_SF_Data_CSI2_Connector (R20.2)
radar_CSI0_D2_P: ADAS_SF_Data_Deserializer_Radar (U2.29), ADAS_SF_Data_CSI2_Connector (R19.1)
radar_CSI0_D3_N: ADAS_SF_Data_Deserializer_Radar (U2.30), ADAS_SF_Data_CSI2_Connector (R14.1)
radar_CSI0_D3_P: ADAS_SF_Data_Deserializer_Radar (U2.31), ADAS_SF_Data_CSI2_Connector (R13.2)
SYNC_CAMERA: ADAS_SF_Data_Deserializer_Camera (U1.17), ADAS_SF_Data_CSI2_Connector (R47.2)
SYNC_RADAR: ADAS_SF_Data_Deserializer_Radar (U2.17), ADAS_SF_Data_CSI2_Connector (R48.2)
UB960_CLK_CAM: ADAS_SF_Data_Deserializer_Camera (U1.5), ADAS_SF_Data_Deserializer_Radar (R33.2)

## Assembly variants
Populated_variant: not fitted C130 C131 C143 C214 C215 C234 C235 C246 C261 C276 C291 J7 J8 J9 J12 J13 J16 J17 J18 J19 J20 J21 R23 R25 R36 R78 R103 R105 R107 R111 R113 R120 R149 R150 R151 R229 R234 R239 R244 R251 TP5 TP6 TP7 TP8 TP9 TP10 TP11 TP12 TP13 TP14 TP16 TP17 TP18 TP19 TP20 TP21 TP22 TP23 TP24 TP25 TP26 TP27 TP28 TP29 TP30 TP31 TP32 TP33 TP34 TP35 TP36 TP37 TP38 TP39 TP44 TP45 TP46 TP47 TP48 TP49 TP50 TP51 TP52 TP53 TP54 TP55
